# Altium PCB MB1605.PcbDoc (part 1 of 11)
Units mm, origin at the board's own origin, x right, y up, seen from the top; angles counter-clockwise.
Board outline 100 x 79.6 mm, 6 copper layers (Top Layer, Signal Layer 1, Signal Layer 2, Signal Layer 3, Signal Layer 4, Bottom Layer), stack 1.549 mm thick; 644 components, 529 nets, 2853 pads, 1462 vias.
Unrouted connection lines stored in the file: 2.
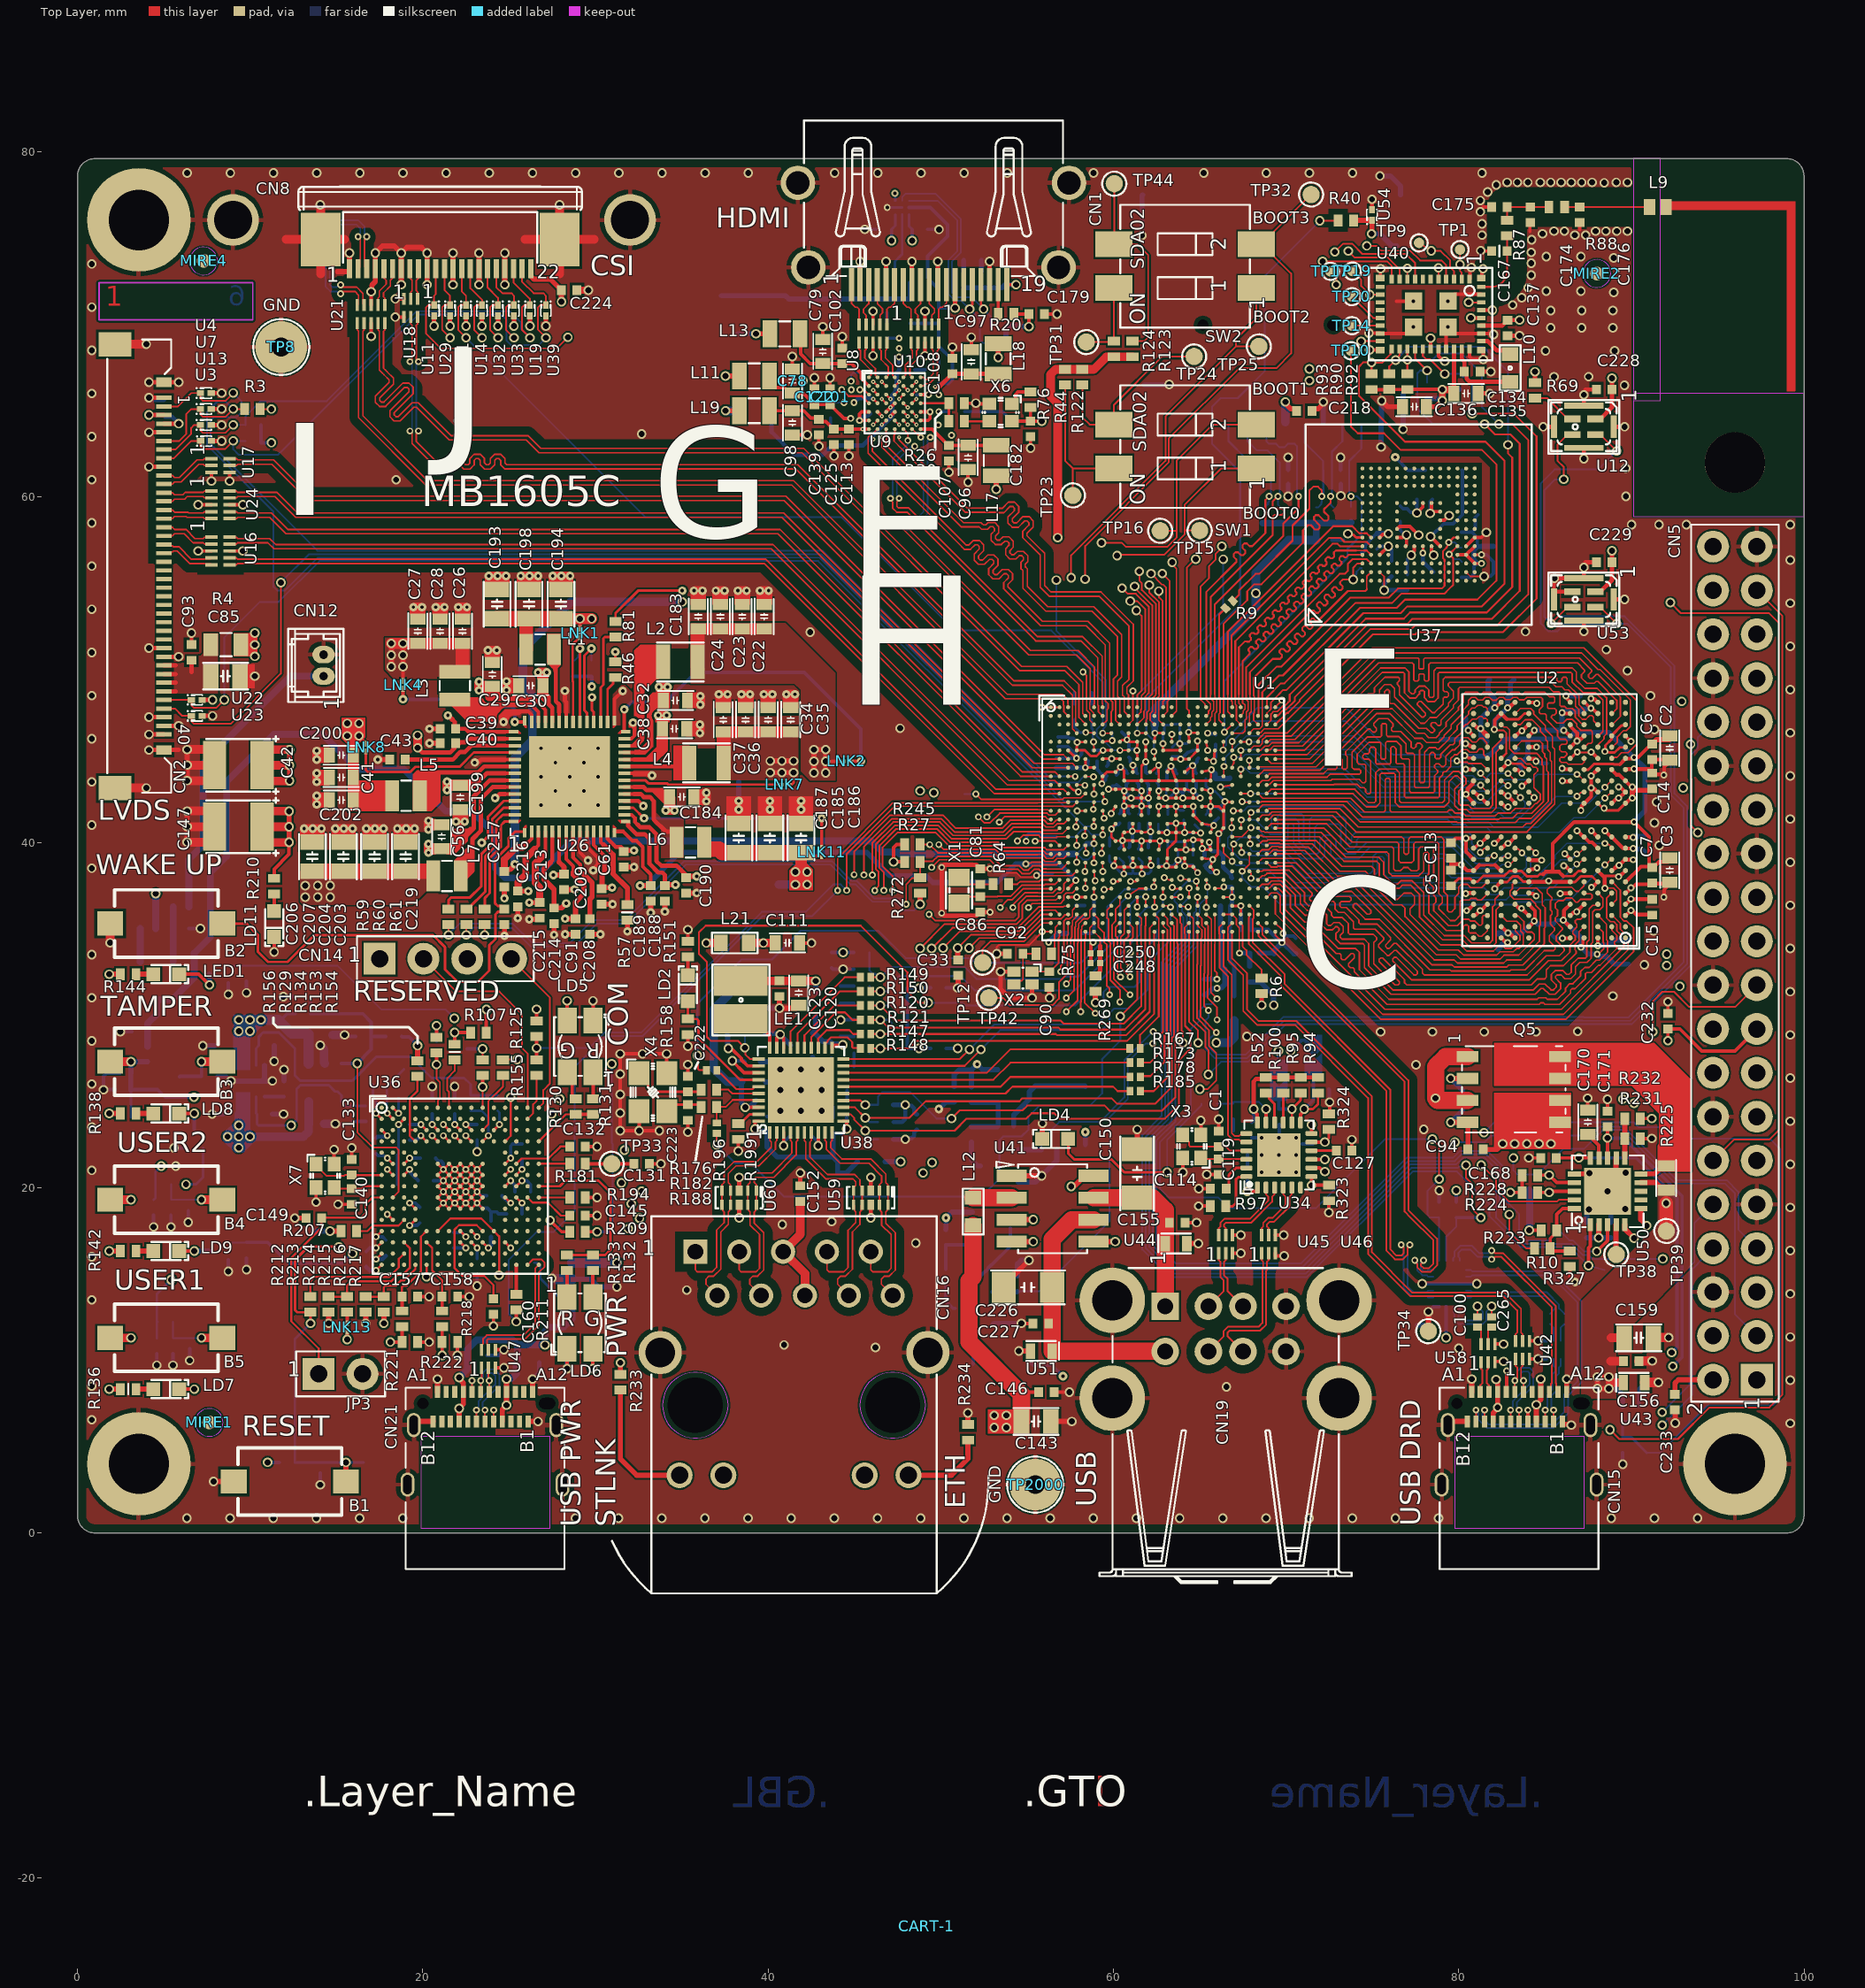
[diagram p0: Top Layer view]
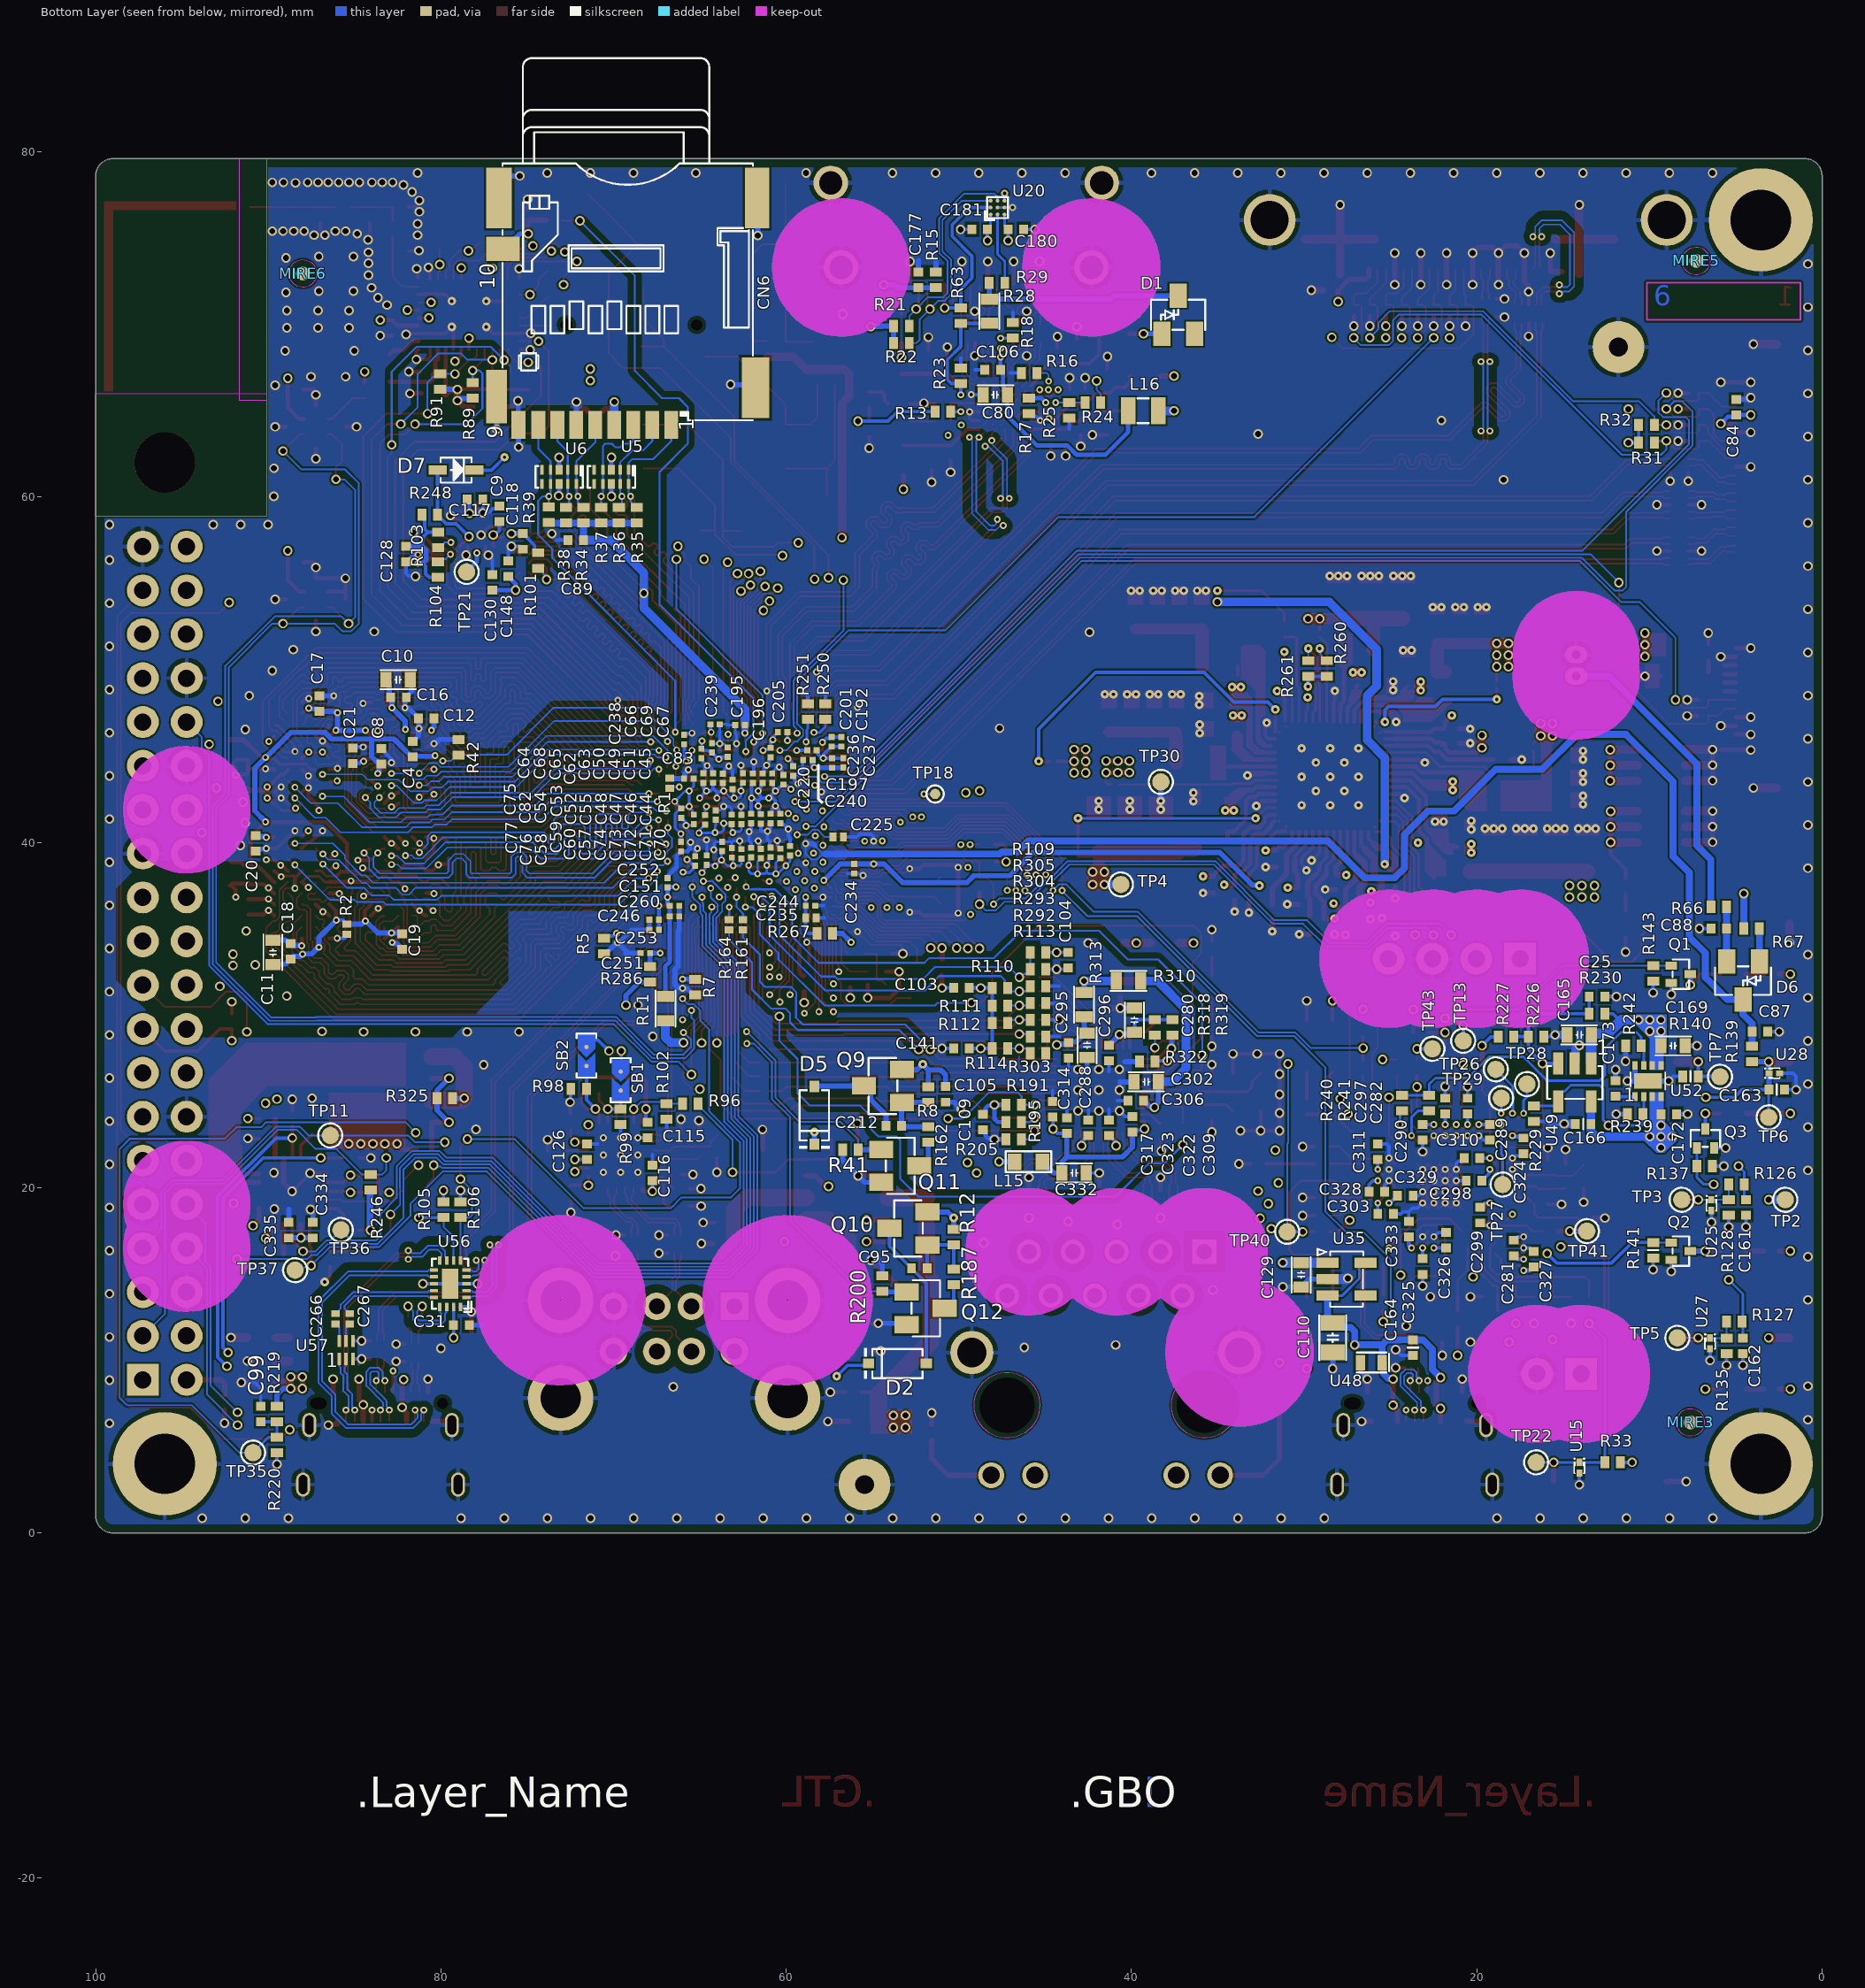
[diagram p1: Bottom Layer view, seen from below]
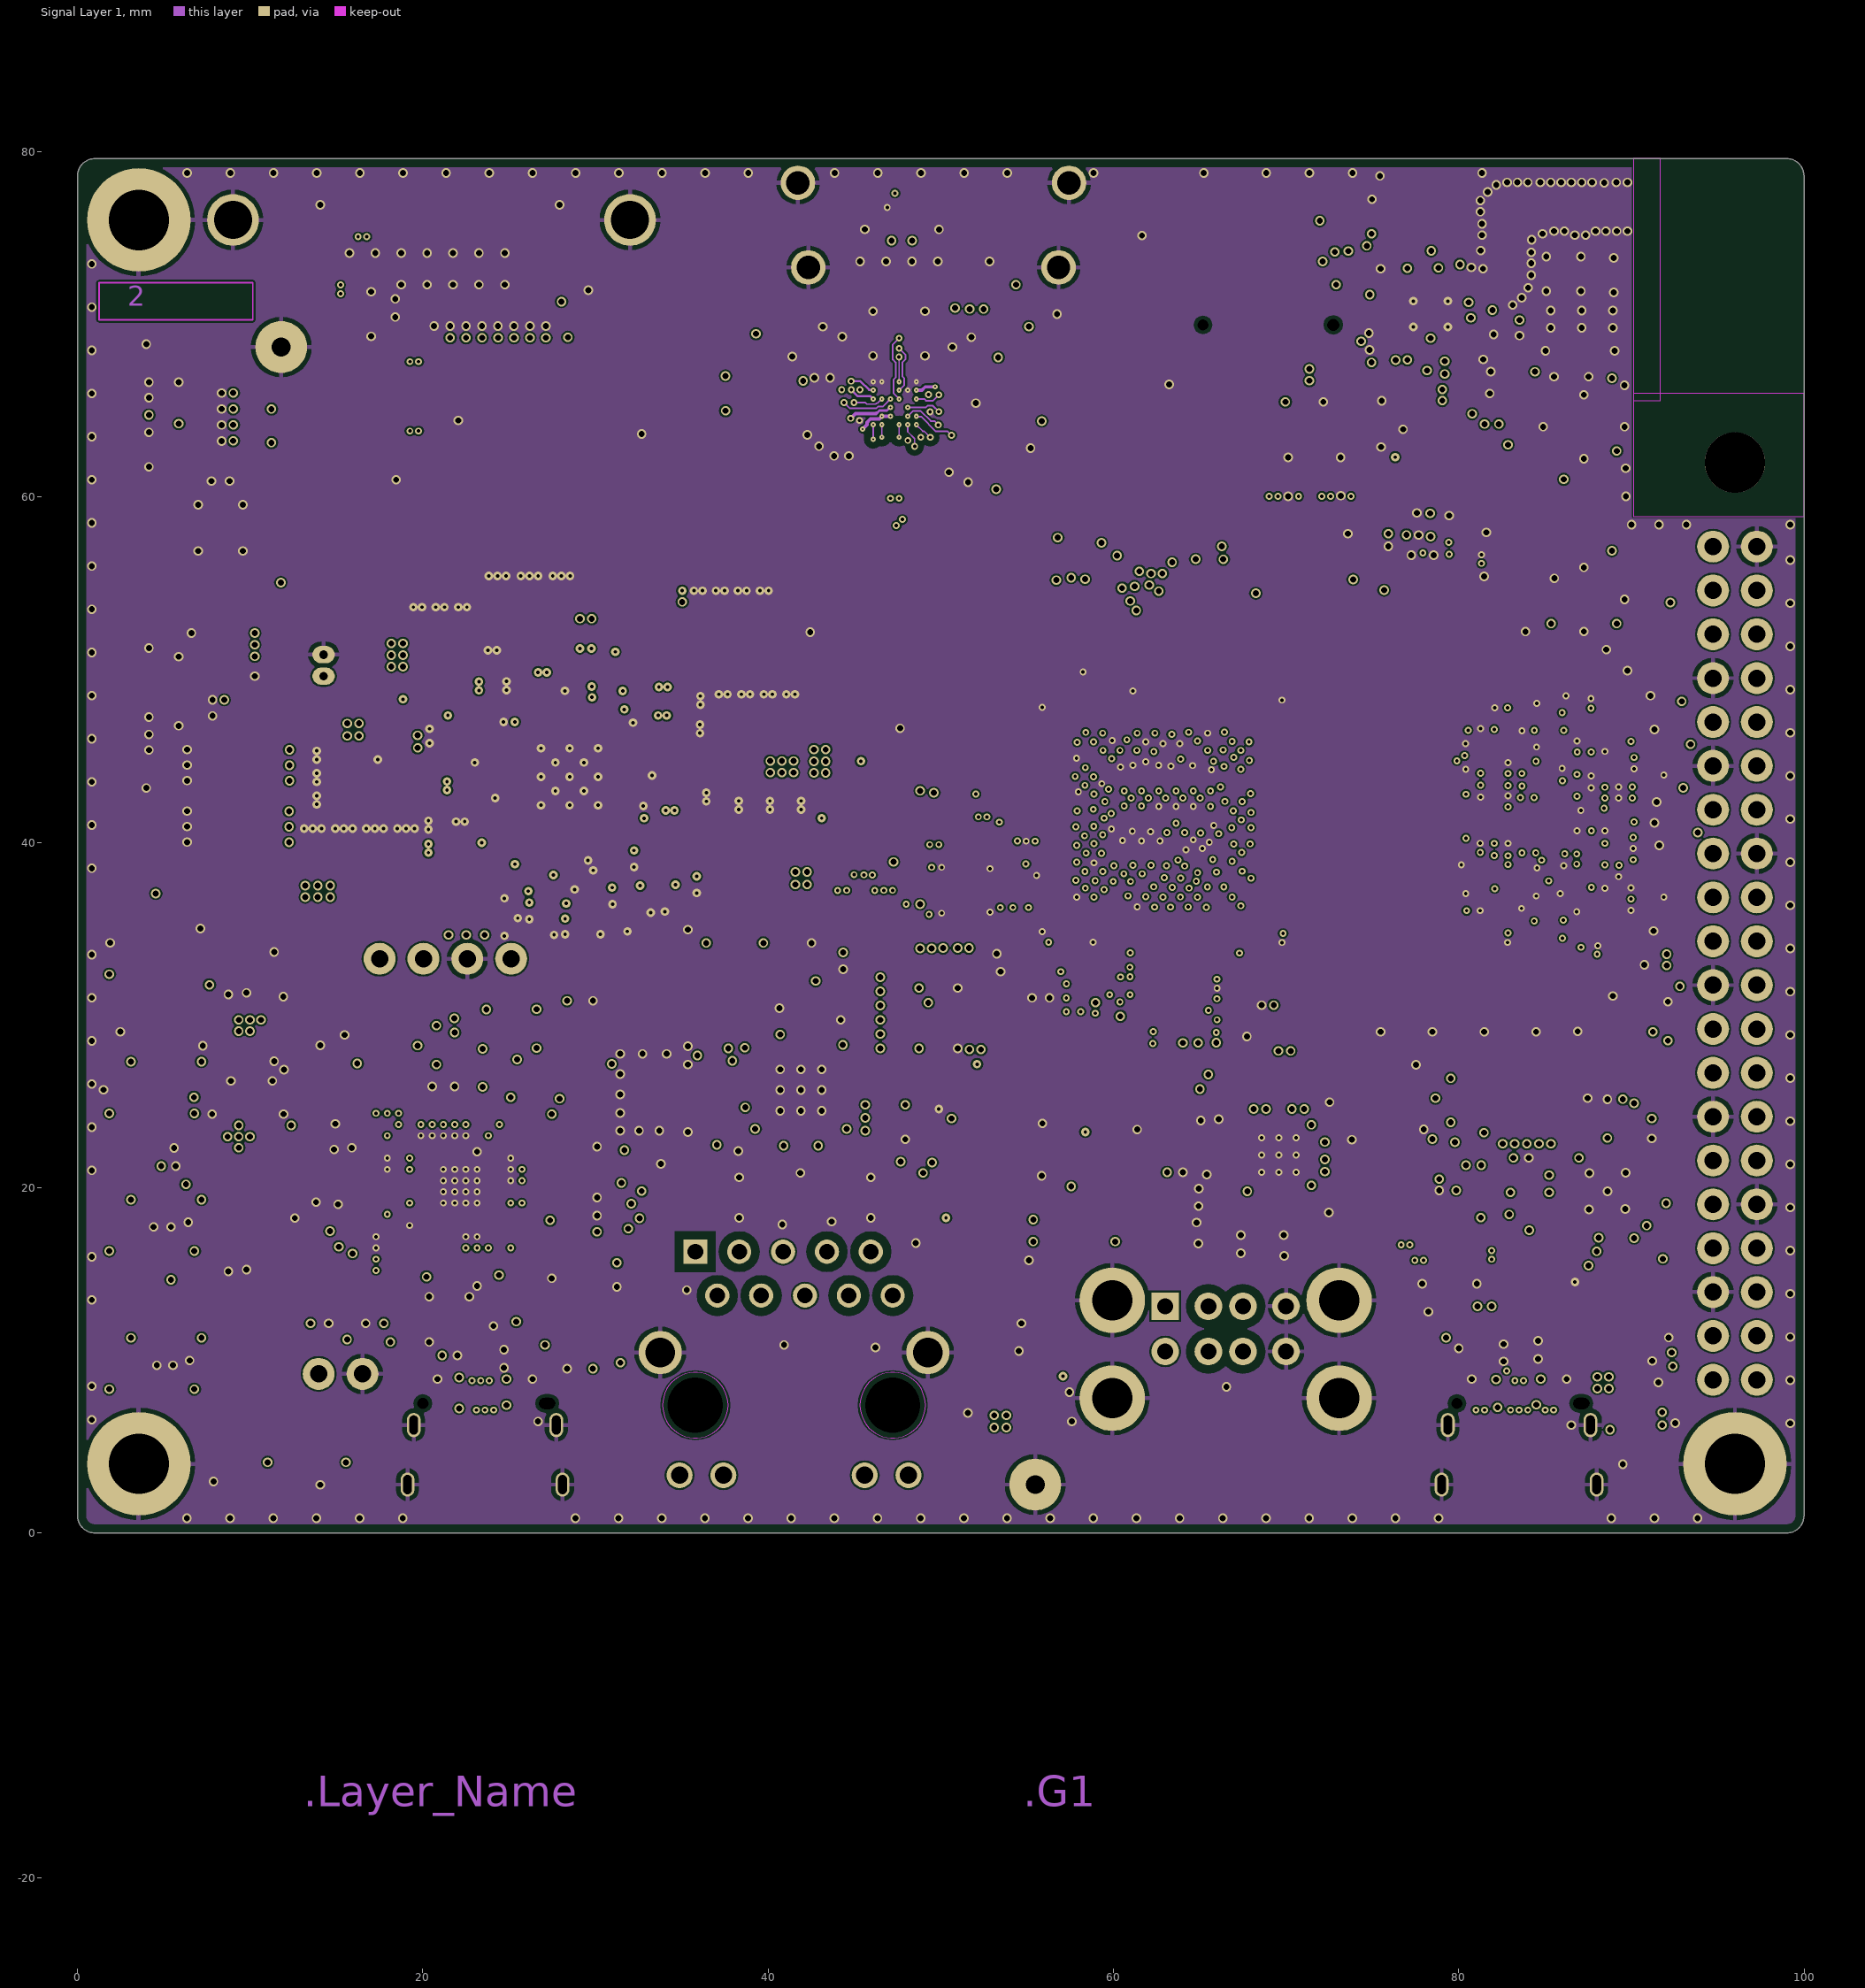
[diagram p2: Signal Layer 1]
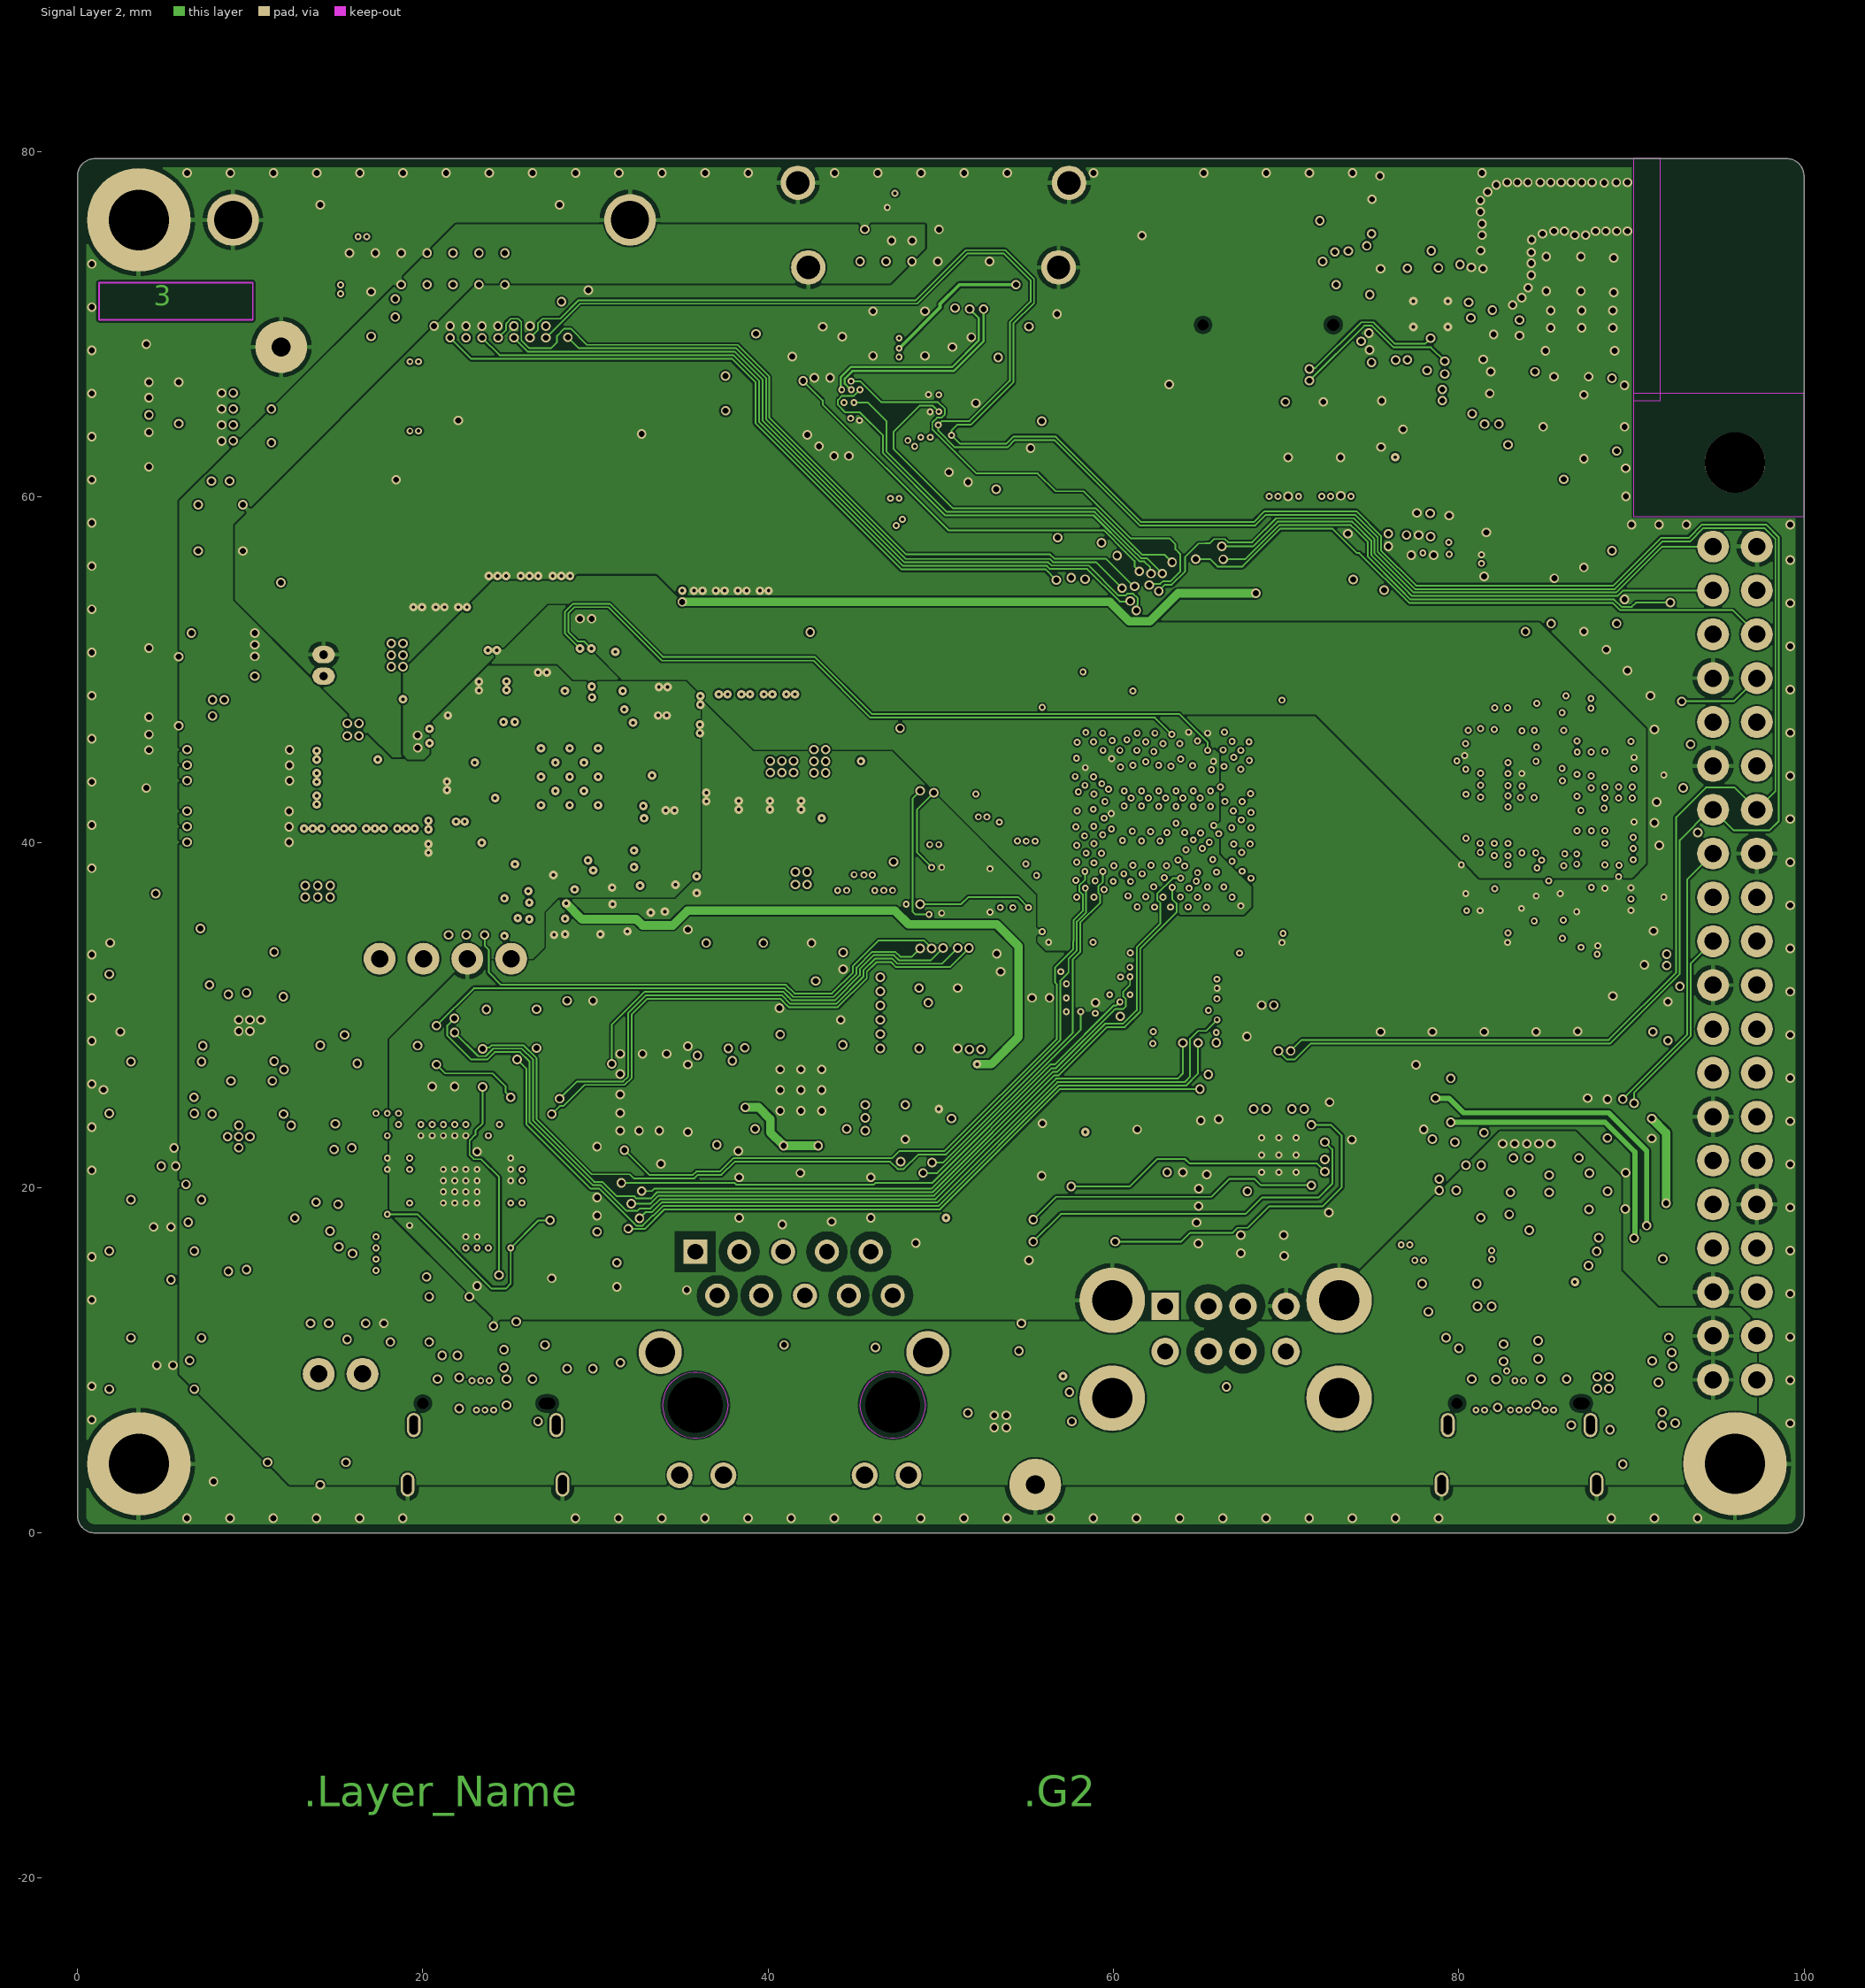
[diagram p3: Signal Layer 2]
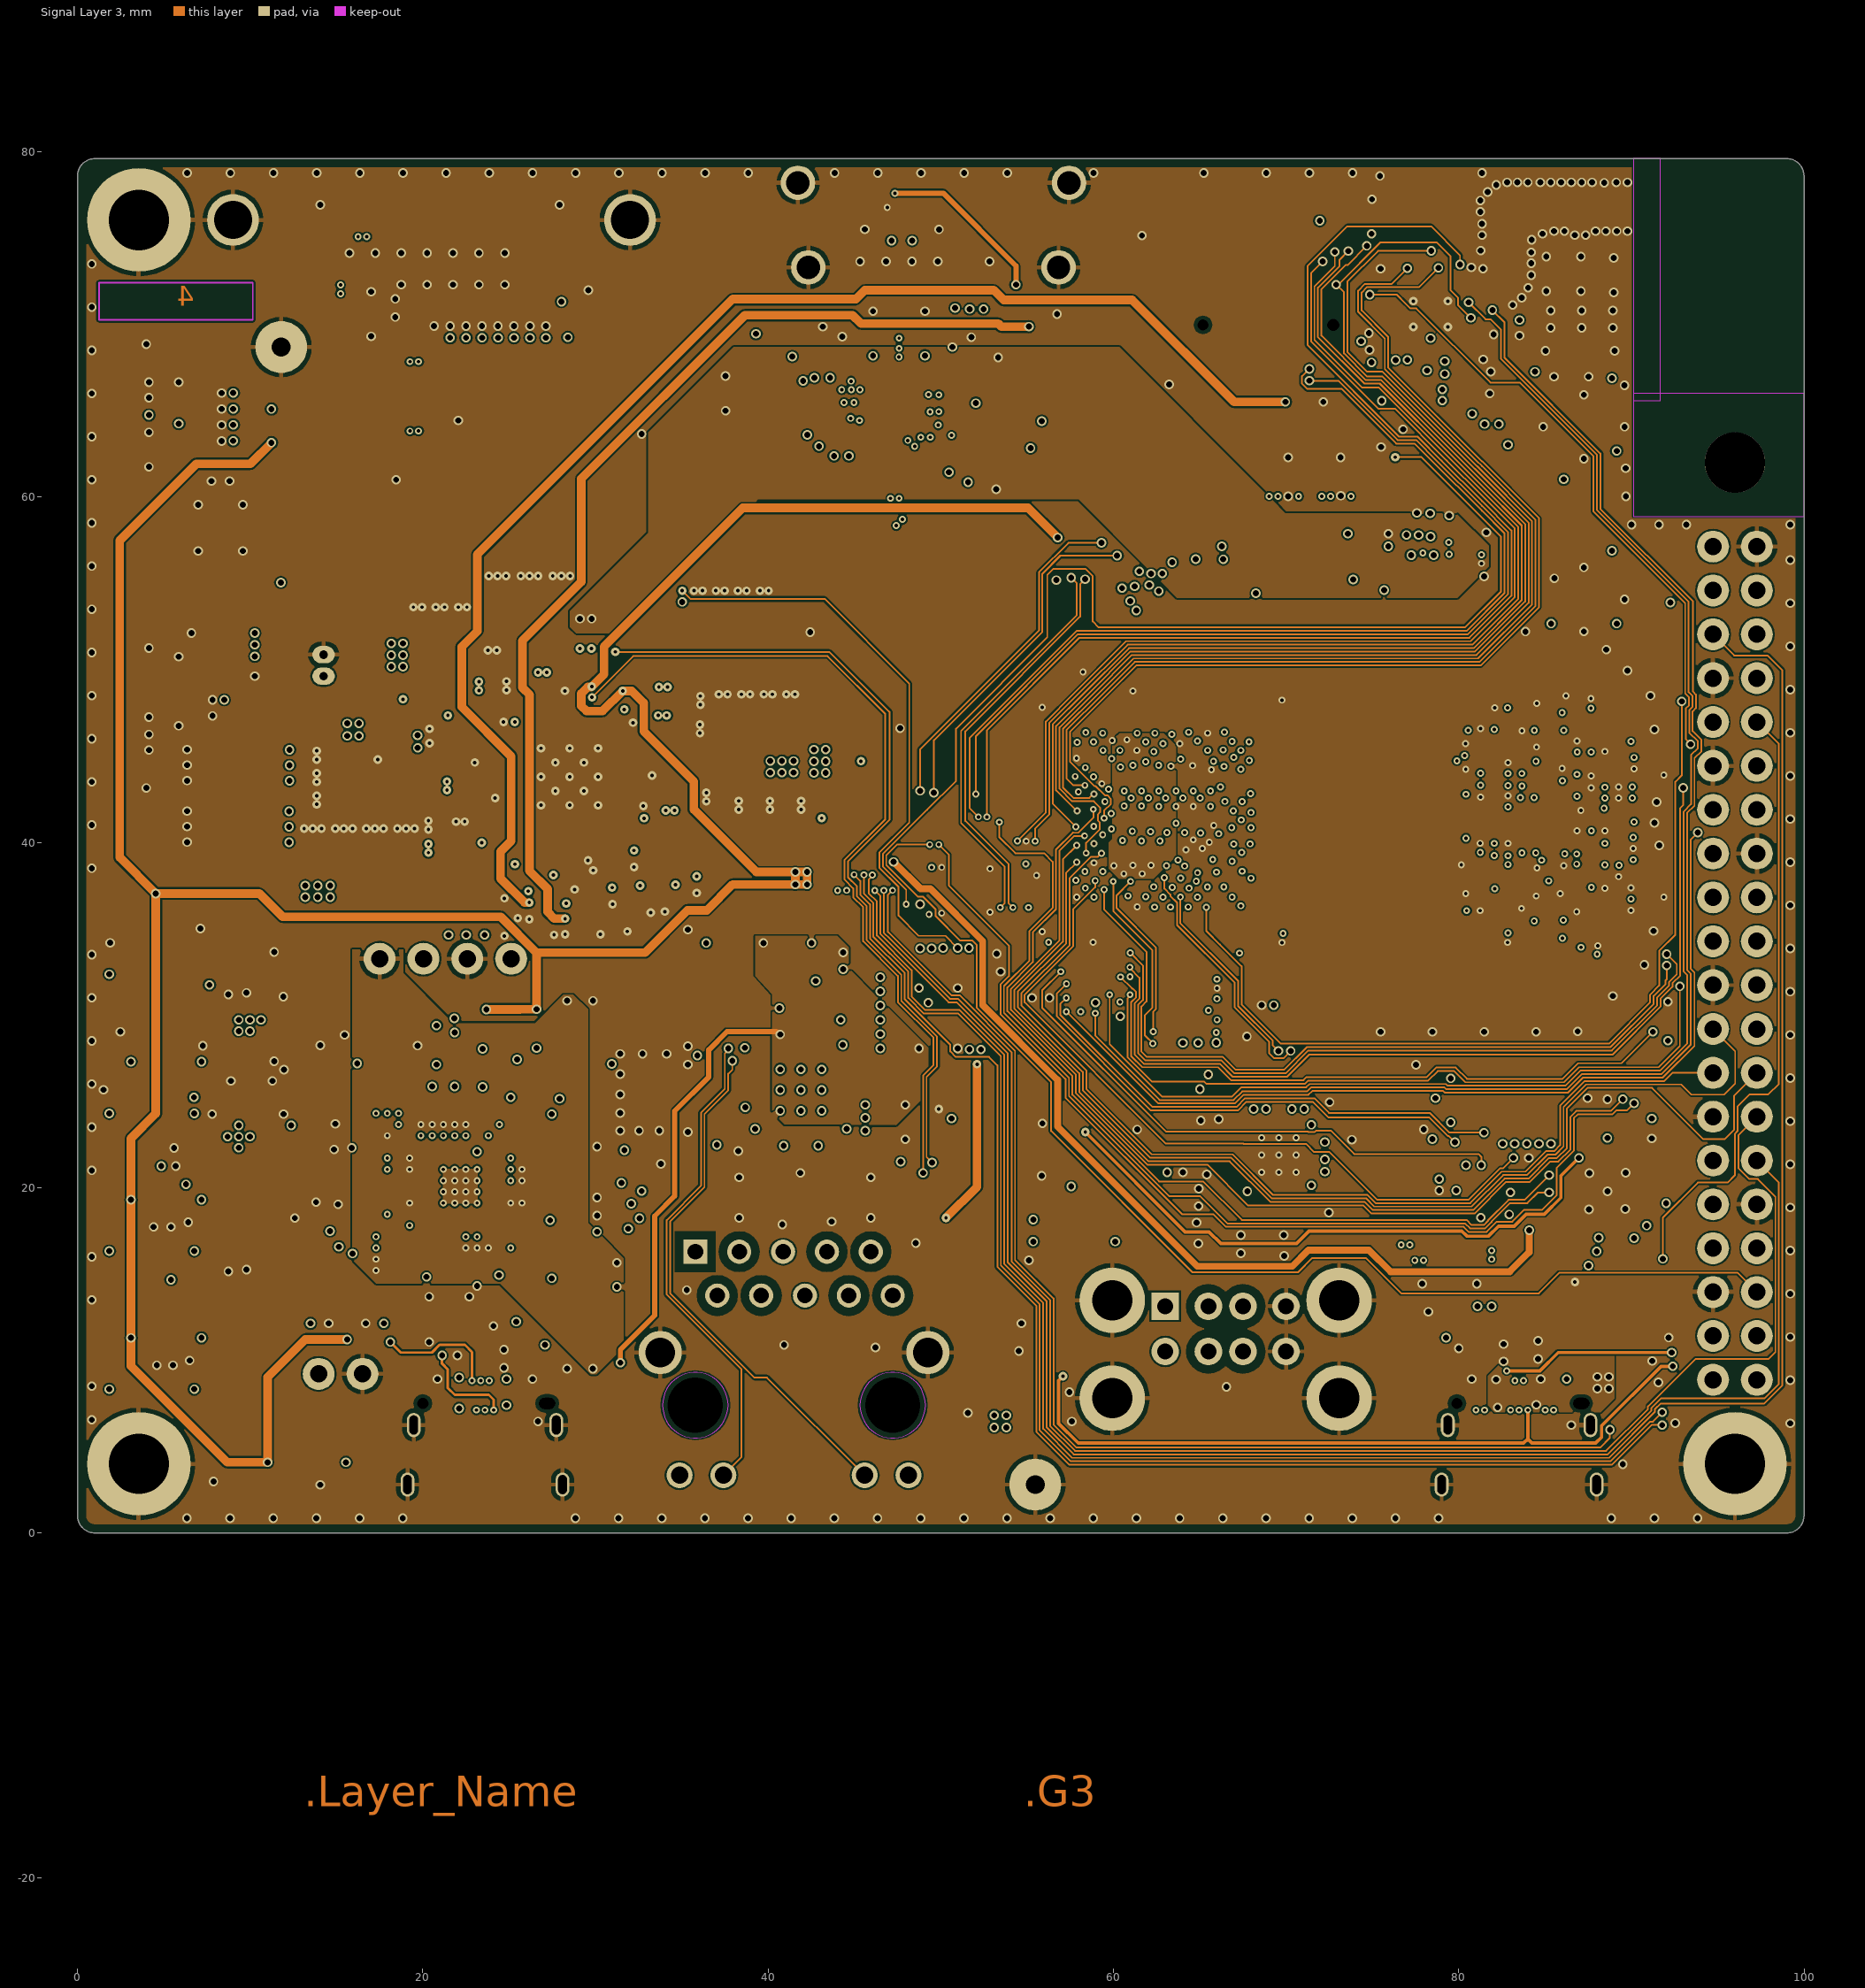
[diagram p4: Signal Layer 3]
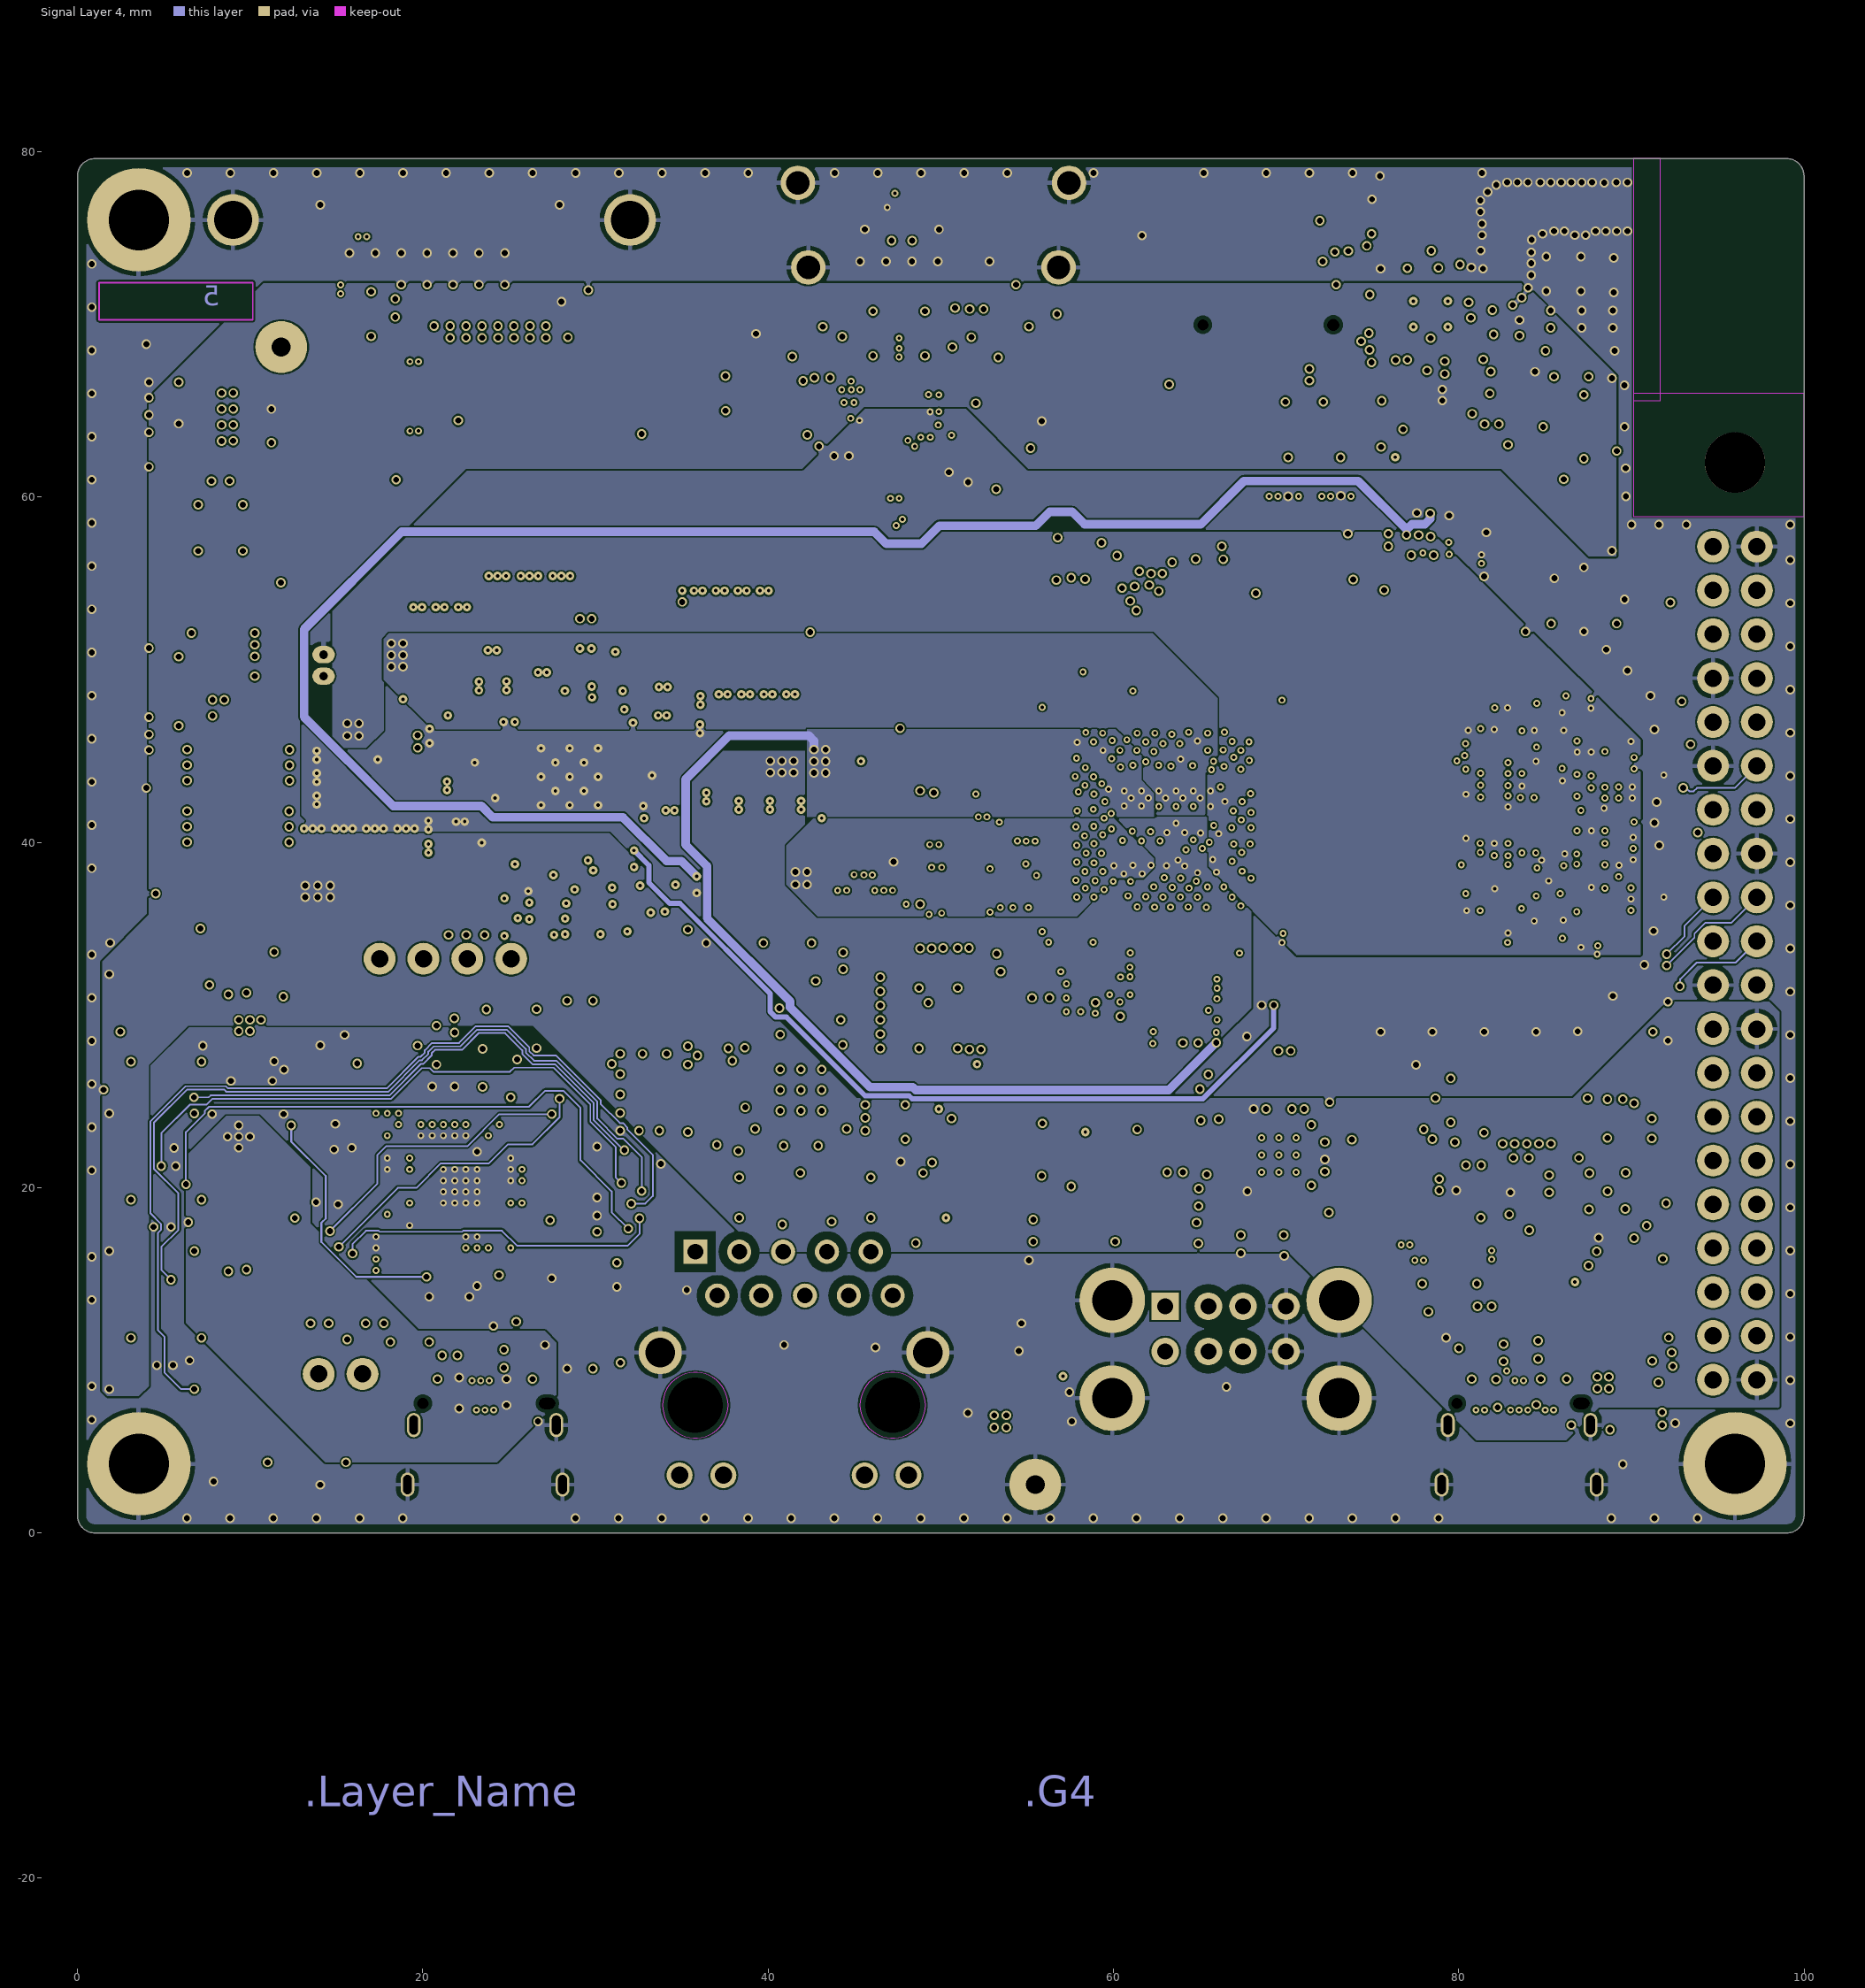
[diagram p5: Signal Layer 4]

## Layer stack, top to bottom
Top Solder: solder mask 0.025, Solder Resist, Dk 3.5
Top Layer: signal copper 0.037
Dielectric 1: prepreg 0.072, Dk 3.8
Signal Layer 1: signal copper 0.035
Dielectric 2: core 0.5, Dk 5
Signal Layer 2: signal copper 0.035
Dielectric 3: core 0.191, Dk 4.3
Signal Layer 3: signal copper 0.035
Dielectric 4: core 0.5, Dk 5
Signal Layer 4: signal copper 0.035
Dielectric 5: prepreg 0.072, Dk 3.8
Bottom Layer: signal copper 0.037
Bottom Solder: solder mask 0.025, Solder Resist, Dk 3.5

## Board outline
0,1 0,78.6 cw(c1,78.6) 1,79.6 99,79.6 cw(c99,78.6) 100,78.6 100,1 cw(c99,1) 99,0 1,0 cw(c1,1)

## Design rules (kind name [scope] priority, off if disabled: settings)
BoardOutlineClearance Silkscreen [OnLayer('Top Overlay') or OnLayer('Bottom Overlay')] p1: gap=0 ignorepadtopadclearanceinfootprint=FALSE
BoardOutlineClearance [All] p2: gap=0.5 ignorepadtopadclearanceinfootprint=FALSE
Clearance via_in_pad_ok [IsVia vs IsPad and ( ((Name='U50-21') or (Name='U30-33') or (Name='U34-25') or (Name='U38-41') or (Name='U26-57') ) or HasFootprint('MOD_WLAN-BT_MURATA_LBEE5KL1YN-814') )] p1: gap=0.3 ignorepadtopadclearanceinfootprint=TRUE except(0: Track-Track Track-SMDPad Track-Via Track-Region SMDPad-Via SMDPad-Hole Via-Region Via-Hole; 0.1: Arc-Arc Arc-Track Arc-SMDPad Arc-THPad Arc-Via Arc-Poly Track-THPad Track-Poly SMDPad-THPad Via-Via Via-Poly Poly-Poly; 0.15: Track-Hole SMDPad-Poly SMDPad-Region Fill-Fill; 0.17: Region-Region; 0.19: Arc-Hole; 0.2: SMDPad-SMDPad THPad-THPad THPad-Via THPad-Poly; 0.25: THPad-Hole Fill-Hole Poly-Hole Region-Hole Text-Hole)
Clearance Clearance_POLY_DIFF-PAIRS [InDifferentialPairClass('100H') or InDifferentialPairClass('90H') vs IsCopperRegion] p2: gap=0.3 ignorepadtopadclearanceinfootprint=TRUE except(0: SMDPad-Hole Via-Hole; 0.1: Arc-Arc Arc-Track Arc-Via Track-Track Track-SMDPad Track-Via Via-Via Via-Poly; 0.12: SMDPad-Via; 0.15: Arc-SMDPad Arc-THPad Track-THPad Track-Region SMDPad-Region; 0.17: Region-Region; 0.2: Track-Hole SMDPad-SMDPad SMDPad-THPad THPad-THPad THPad-Via Poly-Hole; 0.25: Arc-Hole THPad-Hole Fill-Hole Region-Hole Text-Hole; 0.48: Arc-Poly Track-Poly SMDPad-Poly THPad-Poly Fill-Poly Poly-Poly)
Clearance Clearance_POLY_50R [InNetClass('50H') or InNetClass('55H') vs IsCopperRegion] p3: gap=0.3 ignorepadtopadclearanceinfootprint=TRUE except(0: SMDPad-Hole Via-Hole; 0.1: Arc-Arc Arc-Track Arc-SMDPad Arc-THPad Arc-Via Track-SMDPad Track-THPad Track-Via Track-Region SMDPad-SMDPad SMDPad-THPad SMDPad-Via SMDPad-Region THPad-THPad THPad-Via Via-Via Via-Poly Region-Region; 0.2: Track-Track Track-Hole Poly-Hole; 0.25: Arc-Hole THPad-Hole Fill-Hole Region-Hole Text-Hole; 0.33: Arc-Poly Track-Poly SMDPad-Poly THPad-Poly Fill-Poly Poly-Poly)
Clearance Clearance_MCU_DDR [WithinRoom('U_Power_PMIC') or WithinRoom('RoomDefinition_DDR') or WithinRoom('RoomDefinition_eMMC')] p4: gap=0.1 ignorepadtopadclearanceinfootprint=TRUE except(0: SMDPad-Hole Via-Hole; 0.09: Track-Track Track-SMDPad; 0.2: Track-Hole Poly-Hole; 0.25: Arc-Hole THPad-Hole Fill-Hole Region-Hole Text-Hole)
Clearance Clearance_Default_SAME-NETS [Isvia vs IsPad] p5: gap=0.1 ignorepadtopadclearanceinfootprint=TRUE except(0: Track-Track Track-SMDPad Track-Via Track-Region SMDPad-Hole Via-Region Via-Hole; 0.075: SMDPad-Via; 0.15: Track-Hole; 0.19: Arc-Hole; 0.25: THPad-Hole Fill-Hole Poly-Hole Region-Hole Text-Hole)
Clearance Clearance_Default [All] p6: gap=0.1 ignorepadtopadclearanceinfootprint=TRUE except(0: SMDPad-Hole Via-Hole; 0.09: Track-Track; 0.2: Track-Hole Poly-Hole; 0.25: Arc-Hole THPad-Hole Fill-Hole Region-Hole Text-Hole)
ComponentClearance [All] p1: gap=0.2 collisioncheckmode=3 verticalgap=0 showdistances=FALSE
DiffPairsRouting 100H [InDifferentialPairClass('100H')] p1: maxlimit=0.254 minlimit=0.16 mostfreqgap=0.16 toplayer_maxgap=0.16 toplayer_minwidth=0.09 toplayer_maxwidth=0.09 toplayer_prefwidth=0.09 midlayer1_minwidth=0.09 midlayer1_maxwidth=0.381 midlayer1_prefwidth=0.09 midlayer4_minwidth=0.09 midlayer4_maxwidth=0.381 midlayer4_prefwidth=0.09 bottomlayer_maxgap=0.16 bottomlayer_minwidth=0.09 bottomlayer_maxwidth=0.09 bottomlayer_prefwidth=0.09 impedanceprofiledriven=TRUE impedanceprofileid={628B3294-B84C-4222-8D8D-B3EA8745C43E} impedanceprofilevalue=100.000000 maxuncoupledlength=12.7
DiffPairsRouting 90H [InDifferentialPairClass('90H')] p2: maxlimit=0.254 minlimit=0.12 mostfreqgap=0.254 toplayer_maxgap=0.12 toplayer_prefgap=0.12 toplayer_minwidth=0.09 toplayer_maxwidth=0.1 toplayer_prefwidth=0.1 bottomlayer_maxgap=0.12 bottomlayer_prefgap=0.12 bottomlayer_minwidth=0.1 bottomlayer_maxwidth=0.1 bottomlayer_prefwidth=0.1 impedanceprofiledriven=TRUE impedanceprofileid={4FA8ED21-C296-41FC-BFF2-99B46465CFD5} impedanceprofilevalue=90.000000 maxuncoupledlength=12.7
FanoutControl Fanout_BGA [IsBGA] p1: bgadir=Out bgaviamode=Closest fanoutstyle=Auto fanoutdirection=Alternating viagrid=0.025 // Fanout_BGA (Default Rule)
FanoutControl Fanout_LCC [IsLCC] p2: bgadir=Out bgaviamode=Closest fanoutstyle=Auto fanoutdirection=Alternating viagrid=0.025 // Fanout_LCC (Default Rule)
FanoutControl Fanout_SOIC [IsSOIC] p3: bgadir=Out bgaviamode=Closest fanoutstyle=Auto fanoutdirection=Alternating viagrid=0.025 // Fanout_SOIC (Default Rule)
FanoutControl Fanout_Small [(CompPinCount < 5)] p4: bgadir=Out bgaviamode=Closest fanoutstyle=Auto fanoutdirection=OutThenIn viagrid=0.025 // Fanout_Small (Default Rule)
FanoutControl Fanout_Default [All] p5: bgadir=Out bgaviamode=Closest fanoutstyle=Auto fanoutdirection=Alternating viagrid=0.025 // Fanout_Default (Default Rule)
HoleSize [All] p1: absolutevalues=TRUE maxlimit=10 minlimit=0.1 maxpercent=80.000 minpercent=20.000
HoleToHoleClearance [All] p1: gap=0.25 allowstackedmicrovias=TRUE
Length Length__SINGLE_SDMMC1_50R [InxSignalClass('SDMMC1')] p1: maxlimit=100 minlimit=0
Length Length__SINGLE_SDMMC2_50R [InxSignalClass('SDMMC2')] p2: maxlimit=50 minlimit=0
MatchedLengths MatchedLengths_INTRA_LVDS [InxSignalClass('LVDS')] p1: tolerance=5 checknetsindiffpair=FALSE checkdiffpairvsdiffpair=TRUE checkxsignals=TRUE checkothers=TRUE
MatchedLengths MatchedLengths_INTRA_DSI [InxSignalClass('DSI')] p2: tolerance=3 checknetsindiffpair=FALSE checkdiffpairvsdiffpair=TRUE checkxsignals=TRUE checkothers=TRUE
MatchedLengths MatchedLengths_INTRA_CSI [InxSignalClass('CSI')] p3: tolerance=1.3 checknetsindiffpair=FALSE checkdiffpairvsdiffpair=TRUE checkxsignals=TRUE checkothers=TRUE
MatchedLengths MatchedLengths_SDMMC2 [InxSignalClass('SDMMC2')] p4: tolerance=5 checknetsindiffpair=FALSE checkdiffpairvsdiffpair=TRUE checkxsignals=TRUE checkothers=TRUE
MatchedLengths MatchedLengths_SDMMC3 [InxSignalClass('SDMMC3')] p5: tolerance=5 checknetsindiffpair=FALSE checkdiffpairvsdiffpair=TRUE checkxsignals=TRUE checkothers=TRUE
MatchedLengths MatchedLengths_SDMMC1 [InxSignalClass('SDMMC1')] p6: tolerance=5 checknetsindiffpair=FALSE checkdiffpairvsdiffpair=TRUE checkxsignals=TRUE checkothers=TRUE
MatchedLengths MatchedLengths_ETH [InxSignalClass('ETH')] p7: tolerance=10 checknetsindiffpair=FALSE checkdiffpairvsdiffpair=TRUE checkxsignals=TRUE checkothers=TRUE
MaxMinImpedance "Schematic Impedance Constraint_3" [InNet('STLK_USB_CN_N')] p1: minimum=85.00 maximum=95.00
MaxMinImpedance "Schematic Impedance Constraint_2" [InNet('STLK_USB_P')] p2: minimum=85.00 maximum=95.00
MaxMinImpedance "Schematic Impedance Constraint_1" [InNet('STLK_USB_N')] p3: minimum=85.00 maximum=95.00
MaxMinImpedance "Schematic Impedance Constraint" [InNet('STLK_USB_CN_P')] p4: minimum=85.00 maximum=95.00
MinimumSolderMaskSliver MinimumSolderMaskSliver_SOLDER_BRIDGE [All vs HasFootprint('SOLDER-BRIDGE_R0603-0R')] p1: minsoldermaskwidth=0.07
MinimumSolderMaskSliver [All] p2: minsoldermaskwidth=0.075
PlaneConnect [All] p1: planeconnectstyle=Direct reliefexpansion=0.508 reliefentries=4 reliefconductorwidth=0.21 reliefairgap=0.21
PolygonConnect PolygonConnect_Default [All] p1: thpad.connectstyle=Relief thpad.reliefconductorwidth=0.25 thpad.reliefentries=4 thpad.polygonreliefangle="90 Angle" thpad.airgapwidth=0.25 smdpad.connectstyle=NoConnect smdpad.reliefconductorwidth=0.2 smdpad.reliefentries=4 smdpad.polygonreliefangle="90 Angle" smdpad.airgapwidth=0.15 via.connectstyle=Direct via.reliefconductorwidth=0.2 via.reliefentries=4 via.polygonreliefangle="90 Angle" via.airgapwidth=0.2
RoomDefinition RoomDefinition_eMMC [False] p1: confinementstyle=ConfineIn formatcopy=TRUE lockcomponents=FALSE outline 74.056,62.109 81.346,62.109 81.346,54.705 74.056,54.705
RoomDefinition RoomDefinition_DDR [False] p2: confinementstyle=ConfineIn formatcopy=TRUE lockcomponents=FALSE outline 79.028,49.26 90.8,49.26 90.8,33.46 79.028,33.46
RoomDefinition U_Power_PMIC [InComponentClass('U_Power_PMIC')] p3: confinementstyle=ConfineIn formatcopy=TRUE lockcomponents=FALSE outline 55.625,48.575 70.125,48.575 70.125,34.075 55.625,34.075
RoutingLayers RoutingLayers_SINGLE_SDMMC1_50R [InNetClass('NC_SINGLE_SDMMC1_50R')] p1: top layer_v5=TRUE mid layer 1_v5=FALSE mid layer 2_v5=FALSE mid layer 3_v5=FALSE mid layer 4_v5=FALSE bottom layer_v5=TRUE
RoutingLayers RoutingLayers_SINGLE_SDMMC2_50R [InNetClass('NC_SINGLE_SDMMC2_50R')] p2: top layer_v5=TRUE mid layer 1_v5=FALSE mid layer 2_v5=FALSE mid layer 3_v5=FALSE mid layer 4_v5=FALSE bottom layer_v5=TRUE
RoutingLayers RoutingLayers_SINGLE_OCTOSPI_50R [InNetClass('NC_SINGLE_OCTOSPI_50R')] p3: top layer_v5=TRUE mid layer 1_v5=FALSE mid layer 2_v5=FALSE mid layer 3_v5=FALSE mid layer 4_v5=FALSE bottom layer_v5=TRUE
RoutingLayers RoutingLayers_SINGLE_DDR_55R [InNetClass('NC_SINGLE_DDR_55R')] p4: top layer_v5=TRUE mid layer 1_v5=FALSE mid layer 2_v5=FALSE mid layer 3_v5=FALSE mid layer 4_v5=FALSE bottom layer_v5=TRUE
RoutingLayers RoutingLayers_SINGLE_RGMII_ALL_50R_AND_CLK [InNetClass('NC_SINGLE_RGMII_ALL_50R_AND_CLK')] p5: top layer_v5=TRUE mid layer 1_v5=FALSE mid layer 2_v5=FALSE mid layer 3_v5=FALSE mid layer 4_v5=FALSE bottom layer_v5=TRUE
RoutingLayers RoutingLayers_I_SENS_XX_L3 [InNetClass('NC_I_SENS_XXX')] p6: top layer_v5=TRUE mid layer 1_v5=FALSE mid layer 2_v5=TRUE mid layer 3_v5=FALSE mid layer 4_v5=FALSE bottom layer_v5=TRUE
RoutingLayers [All] p7: top layer_v5=TRUE mid layer 1_v5=TRUE mid layer 2_v5=TRUE mid layer 3_v5=TRUE mid layer 4_v5=TRUE bottom layer_v5=TRUE
RoutingVias LVH [InDrillLayerPair('Top Layer - Signal Layer 1')] p1: holewidth=0.15 width=0.4 viastyle="Through Hole" minholewidth=0.15 minwidth=0.4 maxholewidth=0.35 maxwidth=0.6 useviatemplates=TRUE viatemplateguid#1={EFD40917-9999-4685-82FF-413DDD0863D8} viatemplatename#1=v25h10z30x30m0mx40
RoutingVias RoutingVias_Default [InDrillLayerPair('Top Layer - Bottom Layer')] p2: holewidth=0.15 width=0.4 viastyle="Through Hole" minholewidth=0.15 minwidth=0.4 maxholewidth=0.35 maxwidth=0.6 useviatemplates=TRUE viatemplateguid#1={8082EAB8-D593-4669-9C8E-234CD125C595} viatemplateguid#2={45AB699A-D4FA-449C-AC3F-FE300CB3C27D} viatemplateguid#3={0C56A9B8-CF93-463B-97D5-BDCC265789B0} viatemplateguid#4={9F28DA9E-6088-4B56-A5CF-E6C86A3E97F7} viatemplatename#1=v40h20m0mx0 viatemplatename#2=v40h20m25 viatemplatename#3=v50h20m25 viatemplatename#4=v55h35m40mx40
ShortCircuit ShortCircuit_I-SENS-VDDCORE_N [InNet('I_SENS_VDDCORE_N') vs InNet('VDDCORE')] p1: allowed=TRUE
ShortCircuit ShortCircuit_I-SENS-VDDGPU_N [InNet('I_SENS_VDDGPU_N') vs InNet('VDDGPU')] p2: allowed=TRUE
ShortCircuit ShortCircuit_I-SENS-VDDIO_N [InNet('I_SENS_VDDIO_N') vs InNet('VDDIO')] p3: allowed=TRUE
ShortCircuit ShortCircuit_I-SENS-VDDCPU_N [InNet('I_SENS_VDDCPU_N') vs InNet('VDDCPU')] p4: allowed=TRUE
ShortCircuit ShortCircuit_VDD_DDR [InNet('VDD_DDR') And OnLayer('Top Layer') vs InNet('I_SENS_VDD_DDR_4_N') And OnLayer('Top Layer')] p5: allowed=TRUE
ShortCircuit ShortCircuit_Link200 [InPadClass('PC_LINK200')] p6: allowed=TRUE
SilkToSilkClearance [All] p1: silktosilkclearance=0.2
SilkToSolderMaskClearance [IsPad] p1: minsilkscreentomaskgap=0.015 clearancetoexposedcopper=TRUE
SolderMaskExpansion [All] p1: expansion=0.1 istentingtop=FALSE
ViasUnderSMD [InPadClass('PC_VIAS-IN-PAD_OK')] p1: allowed=TRUE
Width Width_SINGLE_50R [InNetClass('50H')] p1: maxlimit=0.199 minlimit=0.078 preferedwidth=0.199 toplayer_minwidth=0.09 toplayer_maxwidth=0.11 toplayer_prefwidth=0.11 bottomlayer_minwidth=0.11 bottomlayer_maxwidth=0.11 bottomlayer_prefwidth=0.11 impedanceprofiledriven=TRUE impedanceprofileid={152E730A-FDA4-4006-BF82-0EE0D5C1A339} impedanceprofilevalue=50.000000 minimp=50.000000 maximp=50.000000 favimp=50.000000
Width Width_SINGLE_DDR_55R [InNetClass('55H')] p2: maxlimit=0.199 minlimit=0.078 preferedwidth=0.199 toplayer_minwidth=0.09 toplayer_maxwidth=0.09 toplayer_prefwidth=0.09 bottomlayer_minwidth=0.09 bottomlayer_maxwidth=0.09 bottomlayer_prefwidth=0.09 impedanceprofiledriven=TRUE impedanceprofileid={D5948A69-504E-4D29-B9E5-77B49DDD78E4} impedanceprofilevalue=55.000000 minimp=50.000000 maximp=50.000000 favimp=50.000000
Width Width_Default [InNetClass('All Nets')] p3: maxlimit=10 minlimit=0.09 preferedwidth=0.1 midlayer1_minwidth=0.1 midlayer2_minwidth=0.1 midlayer3_minwidth=0.1 midlayer4_minwidth=0.1 bottomlayer_minwidth=0.1 minimp=50.000000 maximp=50.000000 favimp=50.000000
15 further rules are at their usual default settings.

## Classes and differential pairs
differential pair class CSI_LVDS_DSI_HDMI: CSI.CK CSI.CKcon CSI.D0 CSI.D0con CSI.D1 CSI.D1con DSI_CLK DSI_D0 DSI_D1 DSI_D2 DSI_D3 HDMI_RX0 HDMI_RX1 HDMI_RX2 HDMI_RXC LVDS1.CLK LVDS1.CLKcon LVDS1.D0 LVDS1.D0con LVDS1.D1 LVDS1.D1con LVDS1.D2 LVDS1.D2con LVDS1.D3 LVDS1.D3con TMDS_CLK TMDS_D0 TMDS_D1 TMDS_D2
differential pair class USB: STLK_USB STLK_USB_CN USB1CN USB2CN USB_DCONN USBDN1 USBDN2 USBDR USBH
differential pair class USB3: RX1 RX2 TX1 TX2 TX10 TX20 USB3RX USB3TX
net class DDR_DATA0-7: DDR_DQ0_A DDR_DQ1_A DDR_DQ2_A DDR_DQ3_A DDR_DQ4_A DDR_DQ5_A DDR_DQ6_A DDR_DQ7_A DDR_DQMI0_A DDR_DQS0_A_N DDR_DQS0_A_P
net class 100H: CSI.CK_N CSI.CK_P CSI.CKcon_N CSI.CKcon_P CSI.D0_N CSI.D0_P CSI.D0con_N CSI.D0con_P CSI.D1_N CSI.D1_P CSI.D1con_N CSI.D1con_P DDR_CLK_A_N DDR_CLK_A_P DDR_CLK_B_N DDR_CLK_B_P DDR_DQS0_A_N DDR_DQS0_A_P DDR_DQS0_B_N DDR_DQS0_B_P DDR_DQS1_A_N DDR_DQS1_A_P DDR_DQS1_B_N DDR_DQS1_B_P DSI_CLK_N DSI_CLK_P DSI_D0_N DSI_D0_P DSI_D1_N DSI_D1_P DSI_D2_N DSI_D2_P DSI_D3_N DSI_D3_P HDMI_RX0_N HDMI_RX0_P HDMI_RX1_N HDMI_RX1_P HDMI_RX2_N HDMI_RX2_P HDMI_RXC_N HDMI_RXC_P LVDS1.CLK_N LVDS1.CLK_P LVDS1.CLKcon_N LVDS1.CLKcon_P LVDS1.D0_N LVDS1.D0_P LVDS1.D0con_N LVDS1.D0con_P LVDS1.D1_N LVDS1.D1_P LVDS1.D1con_N LVDS1.D1con_P LVDS1.D2_N LVDS1.D2_P LVDS1.D2con_N LVDS1.D2con_P LVDS1.D3_N LVDS1.D3_P LVDS1.D3con_N LVDS1.D3con_P RJ452_D1_N RJ452_D1_P RJ452_D2_N RJ452_D2_P RJ452_D3_N RJ452_D3_P RJ452_D4_N RJ452_D4_P TMDS_CLK_N TMDS_CLK_P TMDS_D0_N TMDS_D0_P TMDS_D1_N TMDS_D1_P TMDS_D2_N TMDS_D2_P
net class 90H: NetC100_2 NetC265_2 NetC266_2 NetC267_2 RX1_N RX1_P RX2_N RX2_P STLK_USB_CN_N STLK_USB_CN_P STLK_USB_N STLK_USB_P TX10_N TX10_P TX20_N TX20_P USB1CN_N USB1CN_P USB2CN_N USB2CN_P USB3RX_N USB3RX_P USB3TX_N USB3TX_P USB_DCONN_N USB_DCONN_P USBDN1_N USBDN1_P USBDN2_N USBDN2_P USBDR_N USBDR_P USBH_N USBH_P
net class 55H: DDR_CA0_A DDR_CA0_B DDR_CA1_A DDR_CA1_B DDR_CA2_A DDR_CA2_B DDR_CA3_A DDR_CA3_B DDR_CA4_A DDR_CA4_B DDR_CA5_A DDR_CA5_B DDR_CKE0_A DDR_CKE0_B DDR_CS0_A DDR_CS0_B DDR_DQ0_A DDR_DQ0_B DDR_DQ1_A DDR_DQ1_B DDR_DQ2_A DDR_DQ2_B DDR_DQ3_A DDR_DQ3_B DDR_DQ4_A DDR_DQ4_B DDR_DQ5_A DDR_DQ5_B DDR_DQ6_A DDR_DQ6_B DDR_DQ7_A DDR_DQ7_B DDR_DQ8_A DDR_DQ8_B DDR_DQ9_A DDR_DQ9_B DDR_DQ10_A DDR_DQ10_B DDR_DQ11_A DDR_DQ11_B DDR_DQ12_A DDR_DQ12_B DDR_DQ13_A DDR_DQ13_B DDR_DQ14_A DDR_DQ14_B DDR_DQ15_A DDR_DQ15_B DDR_DQMI0_A DDR_DQMI0_B DDR_DQMI1_A DDR_DQMI1_B DDR_RESETN
differential pair class 100H: CSI.CK CSI.CKcon CSI.D0 CSI.D0con CSI.D1 CSI.D1con DDR_CLK_A DDR_CLK_B DDR_DQS0_A DDR_DQS0_B DDR_DQS1_A DDR_DQS1_B DSI_CLK DSI_D0 DSI_D1 DSI_D2 DSI_D3 HDMI_RX0 HDMI_RX1 HDMI_RX2 HDMI_RXC LVDS1.CLK LVDS1.CLKcon LVDS1.D0 LVDS1.D0con LVDS1.D1 LVDS1.D1con LVDS1.D2 LVDS1.D2con LVDS1.D3 LVDS1.D3con RJ452_D1 RJ452_D2 RJ452_D3 RJ452_D4 TMDS_CLK TMDS_D0 TMDS_D1 TMDS_D2
differential pair class 90H: netc265/netc212 netc266/netc267 RX1 RX2 STLK_USB STLK_USB_CN TX1 TX2 TX10 TX20 USB1CN USB2CN USB3RX USB3TX USB_DCONN USBDN1 USBDN2 USBDR USBH
net class 50H: eMMC.SDMMC2_CK eMMC.SDMMC2_CMD eMMC.SDMMC2_D0 eMMC.SDMMC2_D1 eMMC.SDMMC2_D2 eMMC.SDMMC2_D3 eMMC.SDMMC2_D4 eMMC.SDMMC2_D5 eMMC.SDMMC2_D6 eMMC.SDMMC2_D7 ETH1.CLK ETH1.CLK125 ETH1.GTX_CLK ETH1.MDC ETH1.MDINT ETH1.MDIO ETH1.NRST ETH1.RX_CLK ETH1.RX_CTL ETH1.RXD0 ETH1.RXD1 ETH1.RXD2 ETH1.RXD3 ETH1.TX_CTL ETH1.TXD0 ETH1.TXD1 ETH1.TXD2 ETH1.TXD3 NetCN6_5 NetR120_2 NetR121_2 NetR147_2 NetR148_2 NetR149_2 NetR150_2 NetR161_2 NetR164_2 NetR167_2 NetR173_2 NetR178_2 NetR185_2 SD.SDMMC1_CK SD.SDMMC1_CMD SD.SDMMC1_D0 SD.SDMMC1_D1 SD.SDMMC1_D2 SD.SDMMC1_D3 SD.uSD_DETECT WL.SDMMC3_CK WL.SDMMC3_CMD WL.SDMMC3_D0 WL.SDMMC3_D1 WL.SDMMC3_D2 WL.SDMMC3_D3
net class ETH1.TXD[0..3]: ETH1.TXD0 ETH1.TXD1 ETH1.TXD2 ETH1.TXD3
net class ETH1.RXD[0..3]: ETH1.RXD0 ETH1.RXD1 ETH1.RXD2 ETH1.RXD3
net class WL.SDMMC3_D[0..3]: WL.SDMMC3_D0 WL.SDMMC3_D1 WL.SDMMC3_D2 WL.SDMMC3_D3
net class eMMC.SDMMC2_D[0..7]: eMMC.SDMMC2_D0 eMMC.SDMMC2_D1 eMMC.SDMMC2_D2 eMMC.SDMMC2_D3 eMMC.SDMMC2_D4 eMMC.SDMMC2_D5 eMMC.SDMMC2_D6 eMMC.SDMMC2_D7
component class U_USB_HUB: C1 C114 C115 C116 C119 C126 C127 C143 C146 C150 C155 C226 C227 CN19 L12 LD4 R52 R94 R95 R96 R97 R98 R99 R100 R102 R323 R324 SB1 SB2 U34 U41 U44 U45 U46 U51 X3
component class U_USB3: C31 C94 C95 C99 C100 C105 C156 C159 C168 C170 C171 C212 C265 C266 C267 C334 C335 CN15 D2 D5 Q5 Q9 Q10 Q11 Q12 R5 R6 R7 R8 R10 R12 R41 R105 R106 R162 R187 R200 R219 R220 R223 R225 R231 R232 R325 R327 TP34 TP36 TP37 TP38 TP39 U42 U43 U50 U56 U57 U58
component class U_STLINK_V3EC: C25 C110 C129 C131 C132 C133 C140 C145 C149 C157 C158 C160 C164 C165 C166 C169 C172 C173 C281 C282 C289 C290 C297 C298 C299 C303 C310 C311 C324 C325 C326 C327 C328 C329 C333 CN14 CN21 JP3 LD5 LD6 LNK13 R129 R130 R131 R132 R133 R134 R153 R154 R155 R156 R181 R194 R207 R209 R211 R212 R213 R214 R215 R216 R217 R218 R221 R222 R226 R227 R229 R230 R239 R240 R241 R242 TP26 TP27 TP28 TP29 TP33 U35 U36 U47 U48 U49 U52 X7
component class U_SDcard_eMMC: C9 C89 C117 C118 C128 C130 C148 C218 CN6 D7 HW1 R9 R34 R35 R36 R37 R38 R39 R40 R101 R103 R104 R248 TP21 U5 U6 U37 U54
component class U_MP257_14x14: C33 C81 C86 C90 C92 R27 R31 R32 R64 R75 R107 R125 R205 R224 R228 R245 R246 R260 R261 R272 TP11 TP12 TP13 TP30 TP35 TP40 TP41 TP42 TP43 U1 X1 X2
component class U_LVDS: C84 C85 C93 CN2 R3 R4 U3 U4 U7 U13 U16 U17 U22 U23 U24
component class U_LpDDR4: C2 C3 C4 C5 C6 C7 C8 C10 C11 C12 C13 C14 C15 C16 C17 C18 C19 C20 C21 R1 R2 R42 S U2
component class U_Expansion_Connector: C232 C233 CN5
component class U_CAMERA: C224 CN8 R251 U11 U14 U18 U19 U21 U29 U31 U32 U33 U39
component class U_AUDIO: C228 C229 R69 U12 U53
component class U_HDMI: C78 C79 C80 C96 C97 C98 C101 C102 C106 C107 C108 C113 C122 C125 C139 C177 C179 C180 C181 C182 CN1 D1 L11 L13 L16 L17 L18 L19 R13 R15 R16 R17 R18 R20 R21 R22 R23 R24 R25 R26 R28 R29 R30 R63 R76 R250 U8 U9 U10 U20 X6
component class U_Peripherals: B1 B3 B4 B5 C161 C162 C163 LD7 LD8 LD9 LED1 Q1 Q2 Q3 R33 R44 R122 R123 R124 R126 R127 R128 R135 R136 R137 R138 R139 R140 R141 R142 R143 R144 SW1 SW2 TP2 TP3 TP4 TP5 TP6 TP7 TP15 TP16 TP22 TP23 TP24 TP25 TP31 TP32 TP44 U15 U25 U27 U28
net class SD.SDMMC1_D[0..3]: SD.SDMMC1_D0 SD.SDMMC1_D1 SD.SDMMC1_D2 SD.SDMMC1_D3
net class BOOT[0..3]: BOOT0 BOOT1 BOOT2 BOOT3
component class U_WLAN_BLUETOOTH: C134 C135 C136 C137 C167 C174 C175 C176 L9 L10 R87 R88 R89 R90 R91 R92 R93 TP1 TP9 TP10 TP14 TP17 TP18 TP19 TP20 U40
component class U_Power_MPU: C44 C45 C46 C47 C48 C49 C50 C51 C52 C53 C54 C55 C57 C58 C59 C60 C62 C63 C64 C65 C66 C67 C68 C69 C70 C71 C72 C73 C74 C75 C76 C77 C82 C83 C87 C88 C151 C192 C195 C196 C197 C201 C205 C220 C225 C234 C235 C236 C237 C238 C239 C240 C244 C246 C248 C250 C251 C252 C253 C260 CN12 D6 R11 R66 R67 R267 R269 R286 TP2000
component class U_ETHERNET: C103 C104 C109 C111 C120 C123 C141 C152 C222 C223 C280 C288 C295 C296 C302 C306 C309 C314 C317 C322 C323 C332 CN16 L15 L21 LD2 LE1 R109 R110 R111 R112 R113 R114 R120 R121 R147 R148 R149 R150 R151 R158 R161 R164 R167 R173 R176 R178 R182 R185 R188 R191 R195 R196 R199 R233 R234 R292 R293 R303 R304 R305 R310 R313 R318 R319 R322 U38 U59 U60 X4
component class U_Power_PMIC: B2 C22 C23 C24 C26 C27 C28 C29 C30 C32 C34 C35 C36 C37 C38 C39 C40 C41 C42 C43 C56 C61 C91 C147 C183 C184 C185 C186 C187 C188 C189 C190 C193 C194 C198 C199 C200 C202 C203 C204 C206 C207 C208 C209 C213 C214 C215 C216 C217 C219 L1 L2 L3 L4 L5 L6 L7 LD11 LNK1 LNK2 LNK4 LNK7 LNK8 LNK11 R46 R57 R59 R60 R61 R81 R210 TP8 U26
differential pair netc265/netc212: +NetC100_2 -NetC265_2
differential pair netc266/netc267: +NetC267_2 -NetC266_2
differential pair RX2: +RX2_P -RX2_N
differential pair RX1: +RX1_P -RX1_N
differential pair USB3TX: +USB3TX_P -USB3TX_N
differential pair USB3RX: +USB3RX_P -USB3RX_N
differential pair TX20: +TX20_P -TX20_N
differential pair TX10: +TX10_P -TX10_N
differential pair TX2: +TX2_P -TX2_N
differential pair TX1: +TX1_P -TX1_N
differential pair HDMI_RXC: +HDMI_RXC_P -HDMI_RXC_N
differential pair HDMI_RX2: +HDMI_RX2_P -HDMI_RX2_N
differential pair HDMI_RX1: +HDMI_RX1_P -HDMI_RX1_N
differential pair HDMI_RX0: +HDMI_RX0_P -HDMI_RX0_N
differential pair USBDN1: +USBDN1_P -USBDN1_N
differential pair DDR_DQS1_B: +DDR_DQS1_B_P -DDR_DQS1_B_N
differential pair DDR_DQS1_A: +DDR_DQS1_A_P -DDR_DQS1_A_N
differential pair DDR_DQS0_B: +DDR_DQS0_B_P -DDR_DQS0_B_N
differential pair DDR_DQS0_A: +DDR_DQS0_A_P -DDR_DQS0_A_N
differential pair DDR_CLK_B: +DDR_CLK_B_P -DDR_CLK_B_N
differential pair DDR_CLK_A: +DDR_CLK_A_P -DDR_CLK_A_N
differential pair USBH: +USBH_P -USBH_N
differential pair USBDR: +USBDR_P -USBDR_N
differential pair USBDN2: +USBDN2_P -USBDN2_N
differential pair USB_DCONN: +USB_DCONN_P -USB_DCONN_N
differential pair USB2CN: +USB2CN_P -USB2CN_N
differential pair USB1CN: +USB1CN_P -USB1CN_N
differential pair TMDS_D2: +TMDS_D2_P -TMDS_D2_N
differential pair TMDS_D1: +TMDS_D1_P -TMDS_D1_N
differential pair TMDS_D0: +TMDS_D0_P -TMDS_D0_N
differential pair TMDS_CLK: +TMDS_CLK_P -TMDS_CLK_N
differential pair STLK_USB: +STLK_USB_P -STLK_USB_N
differential pair STLK_USB_CN: +STLK_USB_CN_P -STLK_USB_CN_N
differential pair LVDS1.D3con: +LVDS1.D3con_P -LVDS1.D3con_N
differential pair LVDS1.D2con: +LVDS1.D2con_P -LVDS1.D2con_N
differential pair LVDS1.D1con: +LVDS1.D1con_P -LVDS1.D1con_N
differential pair LVDS1.D0con: +LVDS1.D0con_P -LVDS1.D0con_N
differential pair LVDS1.CLK: +LVDS1.CLK_P -LVDS1.CLK_N
differential pair LVDS1.CLKcon: +LVDS1.CLKcon_P -LVDS1.CLKcon_N
differential pair DSI_D3: +DSI_D3_P -DSI_D3_N
differential pair DSI_D2: +DSI_D2_P -DSI_D2_N
differential pair DSI_D1: +DSI_D1_P -DSI_D1_N
differential pair DSI_D0: +DSI_D0_P -DSI_D0_N
differential pair DSI_CLK: +DSI_CLK_P -DSI_CLK_N
differential pair CSI.D1con: +CSI.D1con_P -CSI.D1con_N
differential pair CSI.D0con: +CSI.D0con_P -CSI.D0con_N
differential pair CSI.CKcon: +CSI.CKcon_P -CSI.CKcon_N
differential pair RJ452_D4: +RJ452_D4_P -RJ452_D4_N
differential pair RJ452_D3: +RJ452_D3_P -RJ452_D3_N
differential pair RJ452_D2: +RJ452_D2_P -RJ452_D2_N
differential pair RJ452_D1: +RJ452_D1_P -RJ452_D1_N
differential pair LVDS1.D3: +LVDS1.D3_P -LVDS1.D3_N
differential pair LVDS1.D2: +LVDS1.D2_P -LVDS1.D2_N
differential pair LVDS1.D1: +LVDS1.D1_P -LVDS1.D1_N
differential pair LVDS1.D0: +LVDS1.D0_P -LVDS1.D0_N
differential pair CSI.D1: +CSI.D1_P -CSI.D1_N
differential pair CSI.D0: +CSI.D0_P -CSI.D0_N
differential pair CSI.CK: +CSI.CK_P -CSI.CK_N

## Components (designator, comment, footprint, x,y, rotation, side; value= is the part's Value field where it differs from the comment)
B1 "SW_PUSH_SMD_2P" SWI_WE_434121025816 12.299,2.979 r180 top value=434121025816
B2 "SW_PUSH_SMD_2P" SWI_WE_434121025816 5.136,35.3 r0 top value=434121025816
B3 "SW_PUSH_SMD_2P" SWI_WE_434121025816 5.136,27.3 r0 top value=434121025816
B4 "SW_PUSH_SMD_2P" SWI_WE_4341x10258x6 5.136,19.3 r0 top value=434111025826
B5 "SW_PUSH_SMD_2P" SWI_WE_4341x10258x6 5.136,11.3 r0 top value=434111025826
C1 "Capacitor" C0402 66.088,22.826 r270 top value=6.8pF
C2 "Capacitor" C0603 92.225,45.46 r90 top value=10uF
C3 "Capacitor" C0603 92.225,38.385 r90 top value=10uF
C4 "100nF" C0402 81.628,45.402 r90 bottom
C5 "100nF" C0402 79.559,37.929 r90 top
C6 "100nF" C0402 91.209,45.24 r270 top
C7 "100nF" C0402 91.209,38.09 r270 top
C8 "100nF" C0402 83.459,44.995 r90 bottom
C9 "Capacitor" C0402 76.615,59.03 r270 bottom value=100nF
C10 "Capacitor" C0603 82.484,49.42 r0 bottom value=10uF
C11 "Capacitor" C0603 89.734,33.62 r270 bottom value=10uF
C12 "100nF" C0402 80.859,47.185 r0 bottom
C13 "100nF" C0402 79.559,39.529 r270 top
C14 "100nF" C0402 91.209,43.565 r90 top
C15 "100nF" C0402 91.209,36.24 r270 top
C16 "100nF" C0402 82.459,48.395 r180 bottom
C17 "100nF" C0402 87.034,48.045 r90 bottom
C18 "100nF" C0402 88.709,33.695 r90 bottom
C19 "100nF" C0402 82.259,34.26 r270 bottom
C20 "100nF" C0402 90.734,39.945 r270 bottom
C21 "100nF" C0402 85.109,45.02 r90 bottom
C22 "Capacitor" C0603 39.775,53.075 r270 top value=22uF
C23 "Capacitor" C0603 38.5,53.075 r270 top value=22uF
C24 "Capacitor" C0603 37.225,53.075 r270 top value=22uF
C25 "Capacitor" C0402 13.042,31.068 r0 bottom value=10nF
C26 "Capacitor" C0603 22.3,52.225 r270 top value=22uF
C27 "Capacitor" C0603 19.7,52.225 r270 top value=22uF
C28 "Capacitor" C0603 21,52.225 r270 top value=22uF
C29 "Capacitor" C0603 24.025,49.725 r270 top value=10uF
C30 "Capacitor" C0603 26.25,49.075 r0 top value=10uF
C31 "Capacitor" C0402 78.818,12.039 r180 bottom value=100nF
C32 "Capacitor" C0603 34.625,48.225 r180 top value=10uF
C33 "Capacitor" C0402 51,32.75 r90 top value=10nF
C34 "Capacitor" C0603 40,47.1 r270 top value=22uF
C35 "Capacitor" C0603 41.3,47.1 r270 top value=22uF
C36 "Capacitor" C0603 38.7,47.1 r270 top value=22uF
C37 "Capacitor" C0603 37.4,47.1 r270 top value=22uF
C38 "Capacitor" C0603 34.575,46.575 r180 top value=10uF
C39 "Capacitor" C0402 21.445,46.575 r0 top value=1uF
C40 "Capacitor" C0402 21.445,45.75 r0 top value=10uF
C41 "Capacitor" C0603 15.275,43.75 r0 top value=22uF
C42 "Cap_POL_TANA" CPOL_TCJ-B_1210_H210 9.311,44.468 r180 top value=100uF
C43 "Capacitor" C0402 18.535,44.8 r0 top value=1uF
C44 "1uF" C0201_MURATA_GRM033_H0P3 60.351,41.38 r270 bottom
C45 "1uF" C0201_MURATA_GRM033_H0P3 60.173,43.62 r270 bottom
C46 "1uF" C0201_MURATA_GRM033_H0P3 60.915,41.38 r90 bottom
C47 "1uF" C0201_MURATA_GRM033_H0P3 61.476,41.356 r270 bottom
C48 "1uF" C0201_MURATA_GRM033_H0P3 62.038,41.382 r90 bottom
C49 "1uF" C0201_MURATA_GRM033_H0P3 61.377,43.712 r270 bottom
C50 "1uF" C0201_MURATA_GRM033_H0P3 61.941,43.713 r270 bottom
C51 "1uF" C0201_MURATA_GRM033_H0P3 60.814,43.713 r270 bottom
C52 "1uF" C0201_MURATA_GRM033_H0P3 63.162,41.332 r270 bottom
C53 "1uF" C0201_MURATA_GRM033_H0P3 64.083,41.581 r270 bottom
C54 "1uF" C0201_MURATA_GRM033_H0P3 64.706,41.304 r270 bottom
C55 "1uF" C0201_MURATA_GRM033_H0P3 62.6,41.325 r270 bottom
C56 "Capacitor" C0603 21.1,40.325 r270 top value=10uF
C57 "1uF" C0201_MURATA_GRM033_H0P3 62.592,39.328 r270 bottom
C58 "1uF" C0201_MURATA_GRM033_H0P3 64.607,38.972 r270 bottom
C59 "1uF" C0201_MURATA_GRM033_H0P3 63.714,39.761 r270 bottom
C60 "1uF" C0201_MURATA_GRM033_H0P3 63.154,39.397 r270 bottom
C61 "Capacitor" C0402 31.625,39.02 r90 top value=4.7uF
C62 "1uF" C0201_MURATA_GRM033_H0P3 63.106,43.353 r90 bottom
C63 "1uF" C0201_MURATA_GRM033_H0P3 62.506,43.73 r270 bottom
C64 "1uF" C0201_MURATA_GRM033_H0P3 64.8,43.721 r270 bottom
C65 "1uF" C0201_MURATA_GRM033_H0P3 63.675,43.709 r90 bottom
C66 "1uF" C0201_MURATA_GRM033_H0P3 64.915,45.146 r90 bottom
C67 "1uF" C0201_MURATA_GRM033_H0P3 63.4,45.225 r270 bottom
C68 "1uF" C0201_MURATA_GRM033_H0P3 64.239,43.722 r270 bottom
C69 "1uF" C0201_MURATA_GRM033_H0P3 64.305,45.477 r270 bottom
C70 "1uF" C0201_MURATA_GRM033_H0P3 59.78,39.51 r90 bottom
C71 "1uF" C0201_MURATA_GRM033_H0P3 60.34,39.36 r270 bottom
C72 "1uF" C0201_MURATA_GRM033_H0P3 60.905,39.423 r270 bottom
C73 "1uF" C0201_MURATA_GRM033_H0P3 61.467,39.349 r90 bottom
C74 "1uF" C0201_MURATA_GRM033_H0P3 62.03,39.408 r270 bottom
C75 "1uF" C0201_MURATA_GRM033_H0P3 66.083,41.692 r90 bottom
C76 "1uF" C0201_MURATA_GRM033_H0P3 65.274,38.923 r270 bottom
C77 "1uF" C0201_MURATA_GRM033_H0P3 66.1,39.75 r270 bottom
C78 "Capacitor" C0603 41.4,66.716 r90 top value=22uF
C79 "Capacitor" C0603 43.164,68.436 r90 top value=22uF
C80 "Capacitor" C0603 47.895,65.92 r0 bottom value=22uF
C81 "Capacitor" C0402 52.285,38.025 r90 top value=3.3pF
C82 "1uF" C0201_MURATA_GRM033_H0P3 65.352,41.328 r90 bottom
C83 "1uF" C0201_MURATA_GRM033_H0P3 65.638,43.698 r180 bottom
C84 "Capacitor" C0402 4.979,65.2 r270 bottom value=100nF
C85 "Capacitor" C0805 8.564,49.625 r180 top value=47uF
C86 "Capacitor" C0402 52.285,36.4 r270 top value=3.3pF
C87 "" C0402 3.606,29.032 r0 bottom value=100nF
C88 "Capacitor" C0402 5.992,35.008 r180 bottom value=2.2uF
C89 "Capacitor" C0402 72.2,57.5 r180 bottom value=100nF
C90 "Capacitor" C0402 56.293,32.06 r90 top value=6.8pF
C91 "Capacitor" C0402 28.85,35.13 r270 top value=4.7uF
C92 "Capacitor" C0402 54.309,33.546 r180 top value=6.8pF
C93 "Capacitor" C0402 6.596,50.999 r270 top value=100nF
C94 "Capacitor" C0402 80.97,22.212 r0 top value=22pF
C95 "Capacitor" C0402 52.297,15.325 r180 bottom value=1nF
C96 "Capacitor" C0603 51.579,62.292 r270 top value=22uF
C97 "Capacitor" C0603 51.769,67.832 r90 top value=22uF
C98 "Capacitor" C0603 41.4,64.299 r270 top value=22uF
C99 "Capacitor" C0402 90.437,6.879 r90 bottom value=10nF
C100 "Capacitor" C0201_H0P3 81.087,12.216 r270 top value=100nF
C101 "Capacitor" C0402 43.589,65.806 r270 top value=100nF
C102 "Capacitor" C0402 44.3,68.186 r90 top value=100nF
C103 "" C0402 49.859,31.565 r180 bottom value=100nF
C104 "" C0402 43.675,33.176 r90 bottom value=100nF
C105 "Capacitor" C0402 50.775,25.4 r270 bottom value=100nF
C106 "Capacitor" C0402 48.045,67.364 r0 bottom value=100nF
C107 "Capacitor" C0402 50.471,62.542 r270 top value=100nF
C108 "Capacitor" C0402 50.676,67.582 r270 top value=100nF
C109 "" C0402 48.614,23.795 r90 bottom value=100nF
C110 "Capacitor" C0805 28.346,11.313 r90 bottom value=2.2uF
C111 "" C0603 41.12,34.17 r180 top value=22uF
C113 "Capacitor" C0402 44.676,63.485 r90 top value=100nF
C114 "Capacitor" C0402 66.073,19.931 r0 top value=100nF
C115 "Capacitor" C0402 68.021,23.338 r90 bottom value=100nF
C116 "Capacitor" C0402 67.757,20.855 r270 bottom value=100nF
C117 "Capacitor" C0402 78.025,59.864 r0 bottom value=2.2uF
C118 "Capacitor" C0402 75.26,57.43 r90 bottom value=100nF
C119 "Capacitor" C0402 66.088,21.201 r90 top value=6.8pF
C120 "" C0603 41.775,31.275 r90 top value=22uF
C122 "Capacitor" C0402 42.689,65.806 r270 top value=100nF
C123 "" C0402 40.65,31.525 r90 top value=100nF
C125 "Capacitor" C0402 43.815,63.485 r90 top value=100nF
C126 "Capacitor" C0402 71.552,22.088 r270 bottom value=100nF
C127 "Capacitor" C0402 73.369,22.14 r180 top value=100nF
C128 "Capacitor" C0402 82.015,56.705 r90 bottom value=2.2uF
C129 "Capacitor" C0603 30.17,14.95 r90 bottom value=10uF
C130 "Capacitor" C0402 77.027,55.055 r270 bottom value=100nF
C131 "Capacitor" C0402 32.665,21.382 r180 top value=20pF
C132 "Capacitor" C0402 28.965,22.382 r180 top value=2.2uF
C133 "Capacitor" C0402 15.885,21.182 r270 top value=5.6pF
C134 "Capacitor" C0402 80.78,67.262 r180 top value=4.7uF
C135 "Capacitor" C0603 80.428,66 r180 top value=10uF
C136 "Capacitor" C0603 77.432,65.231 r0 top value=2.2uF
C137 "" C0402 82.84,69.8 r90 top value=100nF
C139 "Capacitor" C0402 42.943,64.049 r90 top value=100nF
C140 "Capacitor" C0402 15.885,19.482 r270 top value=5.6pF
C141 "" C0402 49.86,28.065 r180 bottom value=100nF
C143 "Capacitor" C0805 55.52,6.456 r180 top value=47uF
C145 "Capacitor" C0402 28.965,18.382 r180 top value=2.2uF
C146 "Capacitor" C0402 56.109,8.16 r180 top value=100nF
C147 "Cap_POL_TANA" CPOL_TCJ-B_1210_H210 9.311,40.906 r180 top value=100uF
C148 "Capacitor" C0402 76.11,55.855 r270 bottom value=2.2uF
C149 "Capacitor" C0402 13.681,18.239 r0 top value=100nF
C150 "Capacitor" C1206_H1P6 61.375,20.822 r270 top value=220uF
C151 "Capacitor" C0201_MURATA_GRM033_H0P3 66.475,36.324 r0 bottom value=1uF
C152 "" C0402 41.865,19.659 r270 top value=100nF
C155 "Capacitor" C0402 63.69,17.976 r180 top value=100nF
C156 "Capacitor" C0402 90,9.952 r180 top value=100pF
C157 "Capacitor" C0402 19.245,13.682 r0 top value=10nF
C158 "Capacitor" C0402 21.565,13.682 r0 top value=10nF
C159 "Capacitor" C0805 90.425,11.302 r180 top value=2.2uF
C160 "Capacitor" C0402 24.09,13.107 r90 top value=2.2uF
C161 "Capacitor" C0402 4.406,18.85 r90 bottom value=100nF
C162 "Capacitor" C0402 4.592,10.837 r90 bottom value=100nF
C163 "Capacitor" C0402 2.633,25.673 r0 bottom value=1nF
C164 "Capacitor" C0402 23.71,10.737 r270 bottom value=100pF
C165 "Capacitor" C0603 14.062,28.848 r180 bottom value=10uF
C166 "Capacitor" C0402 13.84,23.691 r180 bottom value=100nF
C167 "Capacitor" C0402 82.35,74.25 r0 top value=12pF
C168 "Capacitor" C0402 85.2,21.71 r0 top value=470pF
C169 "Capacitor" C0603 8.636,28.217 r0 bottom value=10uF
C170 "Capacitor" C0603 87.475,23.79 r270 top value=100nF
C171 "Capacitor" C0402 88.625,23.985 r270 top value=470pF
C172 "Capacitor" C0402 8.886,24.257 r0 bottom value=100nF
C173 "Capacitor" C0402 11.961,25.736 r270 bottom value=10nF
C174 "Capacitor" C0402 84.15,76.35 r90 top value=12pF
C175 "Capacitor" C0402 82.35,76.8 r0 top value=12pF
C176 "Capacitor" C0402 87,76.35 r90 top value=12pF
C177 "Capacitor" C0402 52.35,72.575 r270 bottom value=100nF
C179 "Capacitor" C0402 55.553,70.6 r180 top value=4.7uF
C180 "Capacitor" C0402 46.702,75.504 r0 bottom value=100nF
C181 "Capacitor" C0402 48.793,75.504 r180 bottom value=100nF
C182 "Capacitor" C0402 55.196,63.945 r90 top value=100nF
C183 "Capacitor" C0603 35.95,53.075 r270 top value=22uF
C184 "Capacitor" C0603 34.997,42.625 r180 top value=10uF
C185 "Capacitor" C0805 40.1,40.25 r270 top value=22uF
C186 "Capacitor" C0805 41.9,40.25 r270 top value=22uF
C187 "Capacitor" C0805 38.3,40.25 r270 top value=22uF
C188 "Capacitor" C0402 34.025,37.04 r90 top value=1uF
C189 "Capacitor" C0402 33.2,37.04 r90 top value=4.7uF
C190 "Capacitor" C0402 35.25,37.515 r270 top value=4.7uF
C192 "Capacitor" C0201_MURATA_GRM033_H0P3 56.8,45.825 r90 bottom value=100nF
C193 "Capacitor" C0805 24.3,53.8 r270 top value=22uF
C194 "Capacitor" C0805 28,53.8 r270 top value=22uF
C195 "Capacitor" C0201_MURATA_GRM033_H0P3 62.675,46.787 r180 bottom value=100nF
C196 "Capacitor" C0201_MURATA_GRM033_H0P3 60.9,45.2 r90 bottom value=100nF
C197 "Capacitor" C0201_MURATA_GRM033_H0P3 58.513,45.342 r0 bottom value=100nF
C198 "Capacitor" C0805 26.15,53.8 r270 top value=22uF
C199 "Capacitor" C0603 22.175,42.6 r90 top value=10uF
C200 "Capacitor" C0603 15.275,45.05 r0 top value=22uF
C201 "Capacitor" C0201_MURATA_GRM033_H0P3 57.375,45.825 r90 bottom value=100nF
C202 "Capacitor" C0603 15.275,42.45 r0 top value=22uF
C203 "Capacitor" C0805 19,39.173 r270 top value=22uF
C204 "Capacitor" C0805 17.2,39.173 r270 top value=22uF
C205 "Capacitor" C0201_MURATA_GRM033_H0P3 60.21,46.38 r0 bottom value=100nF
C206 "Capacitor" C0805 13.6,39.173 r270 top value=22uF
C207 "Capacitor" C0805 15.4,39.173 r270 top value=22uF
C208 "Capacitor" C0402 29.675,35.13 r270 top value=4.7uF
C209 "Capacitor" C0402 30.35,36.87 r90 top value=4.7uF
C212 "Capacitor" C0402 53.775,23.575 r180 bottom value=1nF
C213 "Capacitor" C0402 28.175,37.72 r90 top value=1uF
C214 "Capacitor" C0402 27.6,35.75 r270 top value=4.7uF
C215 "Capacitor" C0402 26.775,36.06 r270 top value=4.7uF
C216 "Capacitor" C0402 25.5,36.725 r90 top value=1uF
C217 "Capacitor" C0402 24.725,37.87 r270 top value=4.7uF
C218 "Capacitor" C0402 71.06,64.99 r180 top value=4.7uF
C219 "Capacitor" C0402 24.727,35.695 r90 top value=10nF
C220 "Capacitor" C0201_MURATA_GRM033_H0P3 59.609,44.131 r90 bottom value=100nF
C222 "" C0402 35.35,26 r270 top value=10pF
C223 "" C0402 35.35,24.35 r90 top value=10pF
C224 "Capacitor" C0402 28.475,71.975 r180 top value=1uF
C225 "Capacitor" C0201_H0P5 56.996,40.309 r0 bottom value=4.7uF
C226 "Capacitor" C1206_H1P6 55.045,14.225 r0 top value=220uF
C227 "Capacitor" C0402 55.795,12.136 r0 top value=100nF
C228 "" C0402 88.425,66.231 r180 top value=100nF
C229 "" C0402 88.425,56.231 r180 top value=100nF
C232 "Capacitor" C0402 92.118,29.64 r90 top value=100nF
C233 "Capacitor" C0402 92.524,7.57 r90 top value=100nF
C234 "Capacitor" C0201_MURATA_GRM033_H0P3 56.064,38.473 r90 bottom value=100nF
C235 "Capacitor" C0201_H0P5 58.575,35.625 r0 bottom value=2.2uF
C236 "Capacitor" C0201_MURATA_GRM033_H0P3 57.35,44.6 r270 bottom value=100nF
C237 "Capacitor" C0201_MURATA_GRM033_H0P3 56.696,44.605 r270 bottom value=100nF
C238 "Capacitor" C0201_MURATA_GRM033_H0P3 65.913,45.951 r270 bottom value=100nF
C239 "Capacitor" C0201_MURATA_GRM033_H0P3 64.125,46.837 r0 bottom value=100nF
C240 "Capacitor" C0201_MURATA_GRM033_H0P3 58.751,44.778 r180 bottom value=100nF
C244 "Capacitor" C0201_MURATA_GRM033_H0P3 58.6,36.331 r0 bottom value=100nF
C246 "Capacitor" C0201_MURATA_GRM033_H0P3 67.65,35.525 r180 bottom value=100nF
C248 "Capacitor" C0201_MURATA_GRM033_H0P3 58.958,33.002 r0 top value=100nF
C250 "Capacitor" C0201_MURATA_GRM033_H0P3 58.958,33.572 r0 top value=1uF
C251 "Capacitor" C0201_MURATA_GRM033_H0P3 68.165,33.588 r180 bottom value=100nF
C252 "Capacitor" C0201_MURATA_GRM033_H0P3 66.87,37.66 r270 bottom value=1uF
C253 "Capacitor" C0201_MURATA_GRM033_H0P3 67.65,34.925 r180 bottom value=100nF
C260 "Capacitor" C0201_MURATA_GRM033_H0P3 66.475,35.714 r0 bottom value=1uF
C265 "Capacitor" C0201_H0P3 81.906,12.216 r270 top value=100nF
C266 "Capacitor" C0201_H0P3 86.111,12.401 r270 bottom value=100nF
C267 "Capacitor" C0201_H0P3 85.292,12.401 r270 bottom value=100nF
C280 "" C0603 39.825,29.7 r90 bottom value=22uF
C281 "Capacitor" C0402 17.865,16.507 r90 bottom value=100nF
C282 "Capacitor" C0402 20.54,24.732 r90 bottom value=100nF
C288 "" C0603 42.575,28.25 r90 bottom value=22uF
C289 "Capacitor" C0402 19.24,23.207 r270 bottom value=100nF
C290 "Capacitor" C0402 23.14,23.207 r270 bottom value=100nF
C295 "" C0402 43.65,27.95 r90 bottom value=100nF
C296 "" C0402 41.3,27.8 r90 bottom value=100nF
C297 "Capacitor" C0402 21.84,24.732 r90 bottom value=100nF
C298 "Capacitor" C0402 20.165,20.407 r0 bottom value=100nF
C299 "Capacitor" C0402 19.815,18.407 r270 bottom value=100nF
C302 "" C0603 39.15,26.125 r180 bottom value=22uF
C303 "Capacitor" C0402 25.29,18.482 r180 bottom value=100nF
C306 "" C0402 39.75,25.05 r180 bottom value=100nF
C309 "" C0402 39.945,23.67 r270 bottom value=100nF
C310 "Capacitor" C0402 20.29,21.707 r0 bottom value=100nF
C311 "Capacitor" C0402 25.74,22.082 r90 bottom value=100nF
C314 "" C0402 44.575,24.55 r270 bottom value=100nF
C317 "" C0402 43.75,23.6 r270 bottom value=100nF
C322 "" C0402 41.3,23.475 r270 bottom value=100nF
C323 "" C0402 42.5,23.475 r270 bottom value=100nF
C324 "Capacitor" C0402 17.29,22.425 r270 bottom value=100nF
C325 "Capacitor" C0402 23.14,15.432 r270 bottom value=100nF
C326 "Capacitor" C0402 21.79,16.957 r90 bottom value=100nF
C327 "Capacitor" C0402 16.715,15.857 r90 bottom value=100nF
C328 "Capacitor" C0402 25.79,19.757 r180 bottom value=100nF
C329 "Capacitor" C0402 24.14,19.532 r180 bottom value=100nF
C332 "" C0603 43.325,20.85 r0 bottom value=22uF
C333 "Capacitor" C0402 23.945,17.607 r90 bottom value=100nF
C334 "Capacitor" C0402 87.425,17.535 r90 bottom value=100nF
C335 "Capacitor" C0402 88.825,17.535 r90 bottom value=4.7uF
CART-1 "Comment" Sheetbox_6L2S 4.1,-28.075 r0 top
CN1 "HDMI_TypeA_DB19_7" CON_HDMI_FCI-AMPHENOL_10029449-001RLF 49.576,80.8 r180 top value=HDMI_A_10029449-001RLF
CN2 "IPEX20455" CON_I-PEX_20455-040E-76 4.5,56 r270 top value=Socket_FFC/FPC_IPEX
CN5 "Header 20x2" CON_SAMTEC_TSW-120-07-G-D 96,33 r90 top
CN6 "microSD-PJS008-2003" CON_MICROSD_YAMAICHI_PJS008-2003-1 69.185,79.775 r90 bottom value=uSD-Card_PJS008-2003-1
CN8 "2-1734592-2" CON_TE-CONNECTIVITY_2-1734592-2_INV 21,74.922 r180 top
CN12 "" CON_MOLEX_53047-0210 14.25,50.25 r90 top value="Header 2x1"
CN14 "Header 4x1" CON_SAMTEC_TSW-104-07-G-S 21.305,33.257 r0 top
CN15 "USB_TYPE_C_Receptacle" CON_USB-TYPEC_AMPHENOL_12401826E412A 83.5,7.5 r0 top value=USB_C_12401826E412A
CN16 "​New part for use of led pulled down on pin 13/14 , schematic more lisible." CON_RJ45_YD_48F-01GYDXNL_LED-P 41.5,0 r0 top locked value=RJ45_48F-01GYDXNL
CN19 "USB_DUAL_TYPEA_5600-3081" CON_DUAL-USB-TYPE-A_CONEXCON_5600-3081 66.5,-2.5 r0 top locked value=USB_A_5600-3081
CN21 "USB_TYPE_C_Receptacle" CON_USB-TYPEC_AMPHENOL_12401826E412A 23.6,7.5 r0 top value=USB_C_12401826E412A
D1 "DIODE_SOT23" DIO_SOT23_SC59_1A_2NC_3K_H1P4 37.3,70.558 r180 bottom value=BAR18FILM
D2 "SCHOTTKY_1A_2K" DIO_SOD123_1A_2K_H1P45 53.563,9.813 r180 bottom value=STPS0530Z
D5 "SCHOTTKY_1A_2K" DIO_SOD123_1A_2K_H1P45 58.375,24.188 r90 bottom value=STPS0530Z
D6 "DIODE_3P_DUAL_COMMON_CATHODE" DIO_SOT23 4.582,31.991 r0 bottom value=BAT54CFILM
D7 "BAT60JFILM" DIO_SOD323 79.125,61.563 r180 bottom
JP3 "Jumper_Header 2x1" CON_SAMTEC_TSW-102-07-G-S 15.235,9.211 r0 top value="Header 2x1"
L1 "Inductor" IND_2016_MURATA_LQM2MPN2R2NG0 26.795,51.175 r180 top value=2.2uH
L2 "Inductor" IND_2520_TOKO_DFE252012P 34.915,50.45 r0 top value=0.68µH
L3 "Inductor" IND_2016_MURATA_LQM2MPN2R2NG0 21.85,49.075 r90 top value=0.68uH
L4 "Inductor" IND_2520_TOKO_DFE252012P 36.425,44.6 r0 top value=0.68µH
L5 "Inductor" IND_2016_MURATA_LQM2MPN2R2NG0 19.025,42.7 r180 top value=0.68uH
L6 "Inductor" IND_2016_MURATA_LQM2MPN2R2NG0 35.5,40 r0 top value=2.2uH
L7 "Inductor" IND_2016_MURATA_LQM2MPN2R2NG0 21.4,38.05 r180 top value=0.68uH
L9 "Inductor" IND_0402_MURATA_LQW15AN2N4C00X 91.525,76.8 r0 top value=2.4nH
L10 "Inductor" L0603 82.98,67.47 r270 top value=2.2uH
L11 "Inductor" IND_0805_MURATA_LQM21 39.202,67.016 r180 top value=10uH
L12 "BEAD" FIL_0603_H0P65 51.875,18.613 r90 top value="26R @ 100Mhz"
L13 "Inductor" IND_0805_MURATA_LQM21 40.97,69.456 r180 top value=10uH
L15 "" FIL_0603_H0P65 45.97,21.5 r0 bottom value="100R @ 100MHz"
L16 "Inductor" IND_0805_MURATA_LQM21 39.325,64.999 r180 bottom value=10uH
L17 "Inductor" IND_0805_MURATA_LQM21 53.214,62.117 r270 top value=10uH
L18 "Inductor" IND_0805_MURATA_LQM21 53.326,68.007 r90 top value=10uH
L19 "Inductor" IND_0805_MURATA_LQM21 39.205,64.999 r180 top value=10uH
L21 "" FIL_0603_H0P65 38.07,34.17 r180 top value="100R @ 100MHz"
LD2 "LED_green" LED_0603_OSRAM_LG-Q396-PS-35_GREEN_1A2K_H0P4 35.35,31.545 r90 top value=GREEN
LD4 "LED_red" LED_0603_VISHAY_VLMS1300-GS08_RED_1A2K_H0P8 56.626,22.826 r180 top value=RED
LD5 "LED_BICOLOR" LED_BI-GR_WE-150141SV73110 29.108,28.175 r180 top value="Green / Red"
LD6 "LED_BICOLOR" LED_BI-GR_WE-150141SV73110 29.1,12.169 r0 top value="Green / Red"
LD7 "LED_red" LED_0603_VISHAY_VLMS1300-GS08_RED_1A2K_H0P8 5.136,8.327 r0 top value=RED
LD8 "LED_green" LED_0603_OSRAM_LG-Q396-PS-35_GREEN_1A2K_H0P4 5.136,24.294 r0 top value=GREEN
LD9 "LED_orange" LED_0603_OSRAM_LO-Q976-PS-25_ORANGE_1A2K_H0P8 5.136,16.327 r0 top value=ORANGE
LD11 "LED_green" LED_0603_OSRAM_LG-Q396-PS-35_GREEN_1A2K_H0P4 11.386,35.272 r270 top value=GREEN
LE1 "" L1210_LQH 38.425,30.875 r90 top value=4.7uH
LED1 "" LED_0603_OSRAM_LB-Q39G-L2OO-35-1_BLUE_1A2K_H0P4 5.136,32.361 r0 top value=BLUE
LNK1 "link_200" LINK200 29.1,52.123 r0 top
LNK2 "link_200" LINK200 44.541,44.7 r90 top
LNK4 "link_200" LINK200 18.85,49.125 r180 top
LNK7 "link_200" LINK200 40.95,43.35 r270 top
LNK8 "link_200" LINK200 16.7,45.498 r0 top
LNK11 "link_200" LINK200 43.1,39.44 r180 top
LNK13 "link_200" LINK200 15.615,11.912 r0 top
MIRE1 "Comment" MIRE_PLACE_SMD_0P8MM 7.625,6.4 r0 top
MIRE2 "Comment" MIRE_PLACE_SMD_0P8MM 88,72.95 r0 top
MIRE3 "Comment" MIRE_PLACE_SMD_0P8MM 7.625,6.4 r180 bottom
MIRE4 "Comment" MIRE_PLACE_SMD_0P8MM 7.3,73.675 r0 top
MIRE5 "Comment" MIRE_PLACE_SMD_0P8MM 7.3,73.675 r180 bottom
MIRE6 "Comment" MIRE_PLACE_SMD_0P8MM 88,72.95 r180 bottom
Q1 "MOSFET_N-CHANNEL" MOS_SC89-3L 8.186,32.361 r270 bottom value=Si1062X
Q2 "MOSFET_N-CHANNEL" MOS_SC89-3L 8.186,16.327 r270 bottom value=Si1062X
Q3 "MOSFET_N-CHANNEL" MOS_SC89-3L 6.763,22.852 r180 bottom value=Si1062X
Q5 "STL40DN3LLH5" PowerFLAT_5x6 83.195,25.687 r90 top
Q9 "MOSFET_P-CHANNEL" MOS_SOT23 54.4,25.888 r90 bottom value=DMP3099L
Q10 "MOSFET_P-CHANNEL" MOS_SOT23 52.922,17.638 r90 bottom value=DMP3099L
Q11 "MOSFET_N-CHANNEL" MOS_SOT23 53.4,21.263 r270 bottom value=DMN3731U
Q12 "MOSFET_N-CHANNEL" MOS_SOT23 51.922,13.013 r270 bottom value=DMN3731U
R1 "Resistor" R0201_H0P23 66.75,43.425 r270 bottom value=240R
R2 "Resistor" R0201_H0P23 85.459,34.97 r90 bottom value=240R
R3 "Resistor" R0402 10.124,65.1 r180 top value=10K
R4 "Resistor" R0805 8.589,51.449 r0 top value=0R
R5 "Resistor" R0402 70.555,33.996 r90 bottom value=200R
R6 "Resistor" R0402 68.584,31.683 r270 top value=200R
R7 "Resistor" R0402 65.274,31.623 r270 bottom value=200R
R8 "Resistor" R0402 51.775,25.388 r90 bottom value=140K
R9 "Resistor" R0201_H0P23 66.702,53.774 r45 top value=22R
R10 "Resistor" R0402 84.85,16.485 r0 top value=0R
R11 "Resistor" R0603 67,30.375 r90 bottom value=0R
R12 "Resistor" R0402 50.297,17.138 r90 bottom value=140K
R13 "Resistor" R0402 50.926,64.947 r180 bottom value=2K
R15 "Resistor" R0402 51.33,72.575 r90 bottom value=10K
R16 "Resistor" R0402 45.924,67.181 r180 bottom value=10K
R17 "Resistor" R0402 45.942,65.276 r90 bottom value=10K
R18 "Resistor" R0402 46.875,69.653 r270 bottom value=1K
R20 "Resistor" R0402 53.776,70.6 r180 top value=0R
R21 "Resistor" R0402 53.326,69.903 r0 bottom value=2K
R22 "Resistor" R0402 53.326,68.92 r0 bottom value=2K
R23 "Resistor" R0402 49.887,67.025 r90 bottom value=0R
R24 "Resistor" R0402 42.234,65.471 r0 bottom value=0R
R25 "Resistor" R0402 43.613,65.029 r270 bottom value=2K
R26 "Resistor" R0402 50.926,65.435 r180 top value=0R
R27 "Resistor" R0402 48.355,38.872 r180 top value=10K
R28 "Resistor" R0603 48.24,70.765 r270 bottom value=27K
R29 "Resistor" R0402 47.79,72.403 r0 bottom value=0R
R30 "Resistor" R0402 50.926,64.395 r0 top value=0R
R31 "Resistor" R0402 10.175,63.15 r0 bottom value=1K5
R32 "Resistor" R0402 10.175,64.175 r0 bottom value=1K5
R33 "Resistor" R0402 12.136,4.09 r180 bottom value=10K
R34 "Resistor" R0402 71.75,58.943 r270 bottom value=10K
R35 "Resistor" R0402 68.661,58.943 r270 bottom value=47K
R36 "Resistor" R0402 69.7,58.943 r270 bottom value=47K
R37 "Resistor" R0402 70.725,58.943 r270 bottom value=47K
R38 "Resistor" R0402 72.75,58.943 r270 bottom value=47K
R39 "Resistor" R0402 73.754,58.98 r270 bottom value=47K
R40 "Resistor" R0402 73.465,76.025 r0 top value=0R
R41 "Resistor" R0402 56.275,22.2 r180 bottom value=100K
R42 "Resistor" R0402 78.984,45.51 r270 bottom value=10K
R44 "Resistor" R0402 57.2,66.95 r90 top value=1K
R46 "" R0402 31.15,49.998 r270 top value=0R
R52 "Resistor" R0402 68.82,25.937 r90 top value=10K
R57 "" R0402 31.85,35.95 r90 top value=0R
R59 "" R0402 21.48,35.695 r90 top value=0R
R60 "" R0402 22.53,35.695 r90 top value=0R
R61 "" R0402 23.58,35.695 r90 top value=0R
R63 "Resistor" R0402 49.889,70.5 r270 bottom value=0R
R64 "" R0402 53.485,37.575 r180 top value=0R
R66 "Resistor" R0402 5.992,36.26 r180 bottom value=20R
R67 "Resistor" R0402 4.082,35.008 r0 bottom value=0R
R69 "Resistor" R0402 84.416,66.181 r270 top value=10K
R75 "" R0402 55.959,33.546 r0 top value=0R
R76 "Resistor" R0402 55.196,65.635 r90 top value=10K
R81 "" R0402 31.163,52.348 r270 top value=0R
R87 "Resistor" R0402 82.8,75.575 r270 top value=0R
R88 "Resistor" R0402 85.675,76.8 r180 top value=0R
R89 "Resistor" R0402 78.164,66.184 r90 bottom value=47K
R90 "Resistor" R0402 75.975,66.682 r90 top value=47K
R91 "Resistor" R0402 80.045,66.692 r90 bottom value=47K
R92 "Resistor" R0402 77.025,66.679 r90 top value=47K
R93 "Resistor" R0402 74.95,66.679 r90 top value=47K
R94 "Resistor" R0402 71.85,25.937 r90 top value=100K
R95 "Resistor" R0402 70.844,25.937 r90 top value=100K
R96 "Resistor" R0402 65.549,24.859 r0 bottom value=1K
R97 "Resistor" R0402 66.069,18.927 r0 top value=12K
R98 "Resistor" R0402 72.027,25.712 r180 bottom value=100K
R99 "Resistor" R0402 69.6,24.1 r90 bottom value=100K
R100 "Resistor" R0402 69.837,25.937 r270 top value=10K
R101 "Resistor" R0402 74.375,56.325 r90 bottom value=10K
R102 "Resistor" R0402 66.934,24.409 r90 bottom value=100K
R103 "Resistor" R0402 80.171,57.511 r90 bottom value=10K
R104 "Resistor" R0402 80.175,55.805 r270 bottom value=10K
R105 "Resistor" R0402 79.854,18.715 r90 bottom value=100K
R106 "Resistor" R0402 78.868,18.715 r270 bottom value=100K
R107 "Resistor" R0402 23.225,28.982 r0 top value=10K
R109 "" R0402 45.42,33.625 r180 bottom value=4K7
R110 "" R0402 47.62,31.565 r0 bottom value=4K7
R111 "" R0402 47.62,30.545 r0 bottom value=4K7
R112 "" R0402 47.62,29.53 r0 bottom value=4K7
R113 "" R0402 45.42,28.75 r0 bottom value=4K7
